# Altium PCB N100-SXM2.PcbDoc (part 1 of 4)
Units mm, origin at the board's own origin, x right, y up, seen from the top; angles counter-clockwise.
Board outline 120 x 145 mm, 4 copper layers (Top Layer, GND, PWR, Bottom Layer), stack 0.603 mm thick; 267 components, 207 nets, 1440 pads, 915 vias.
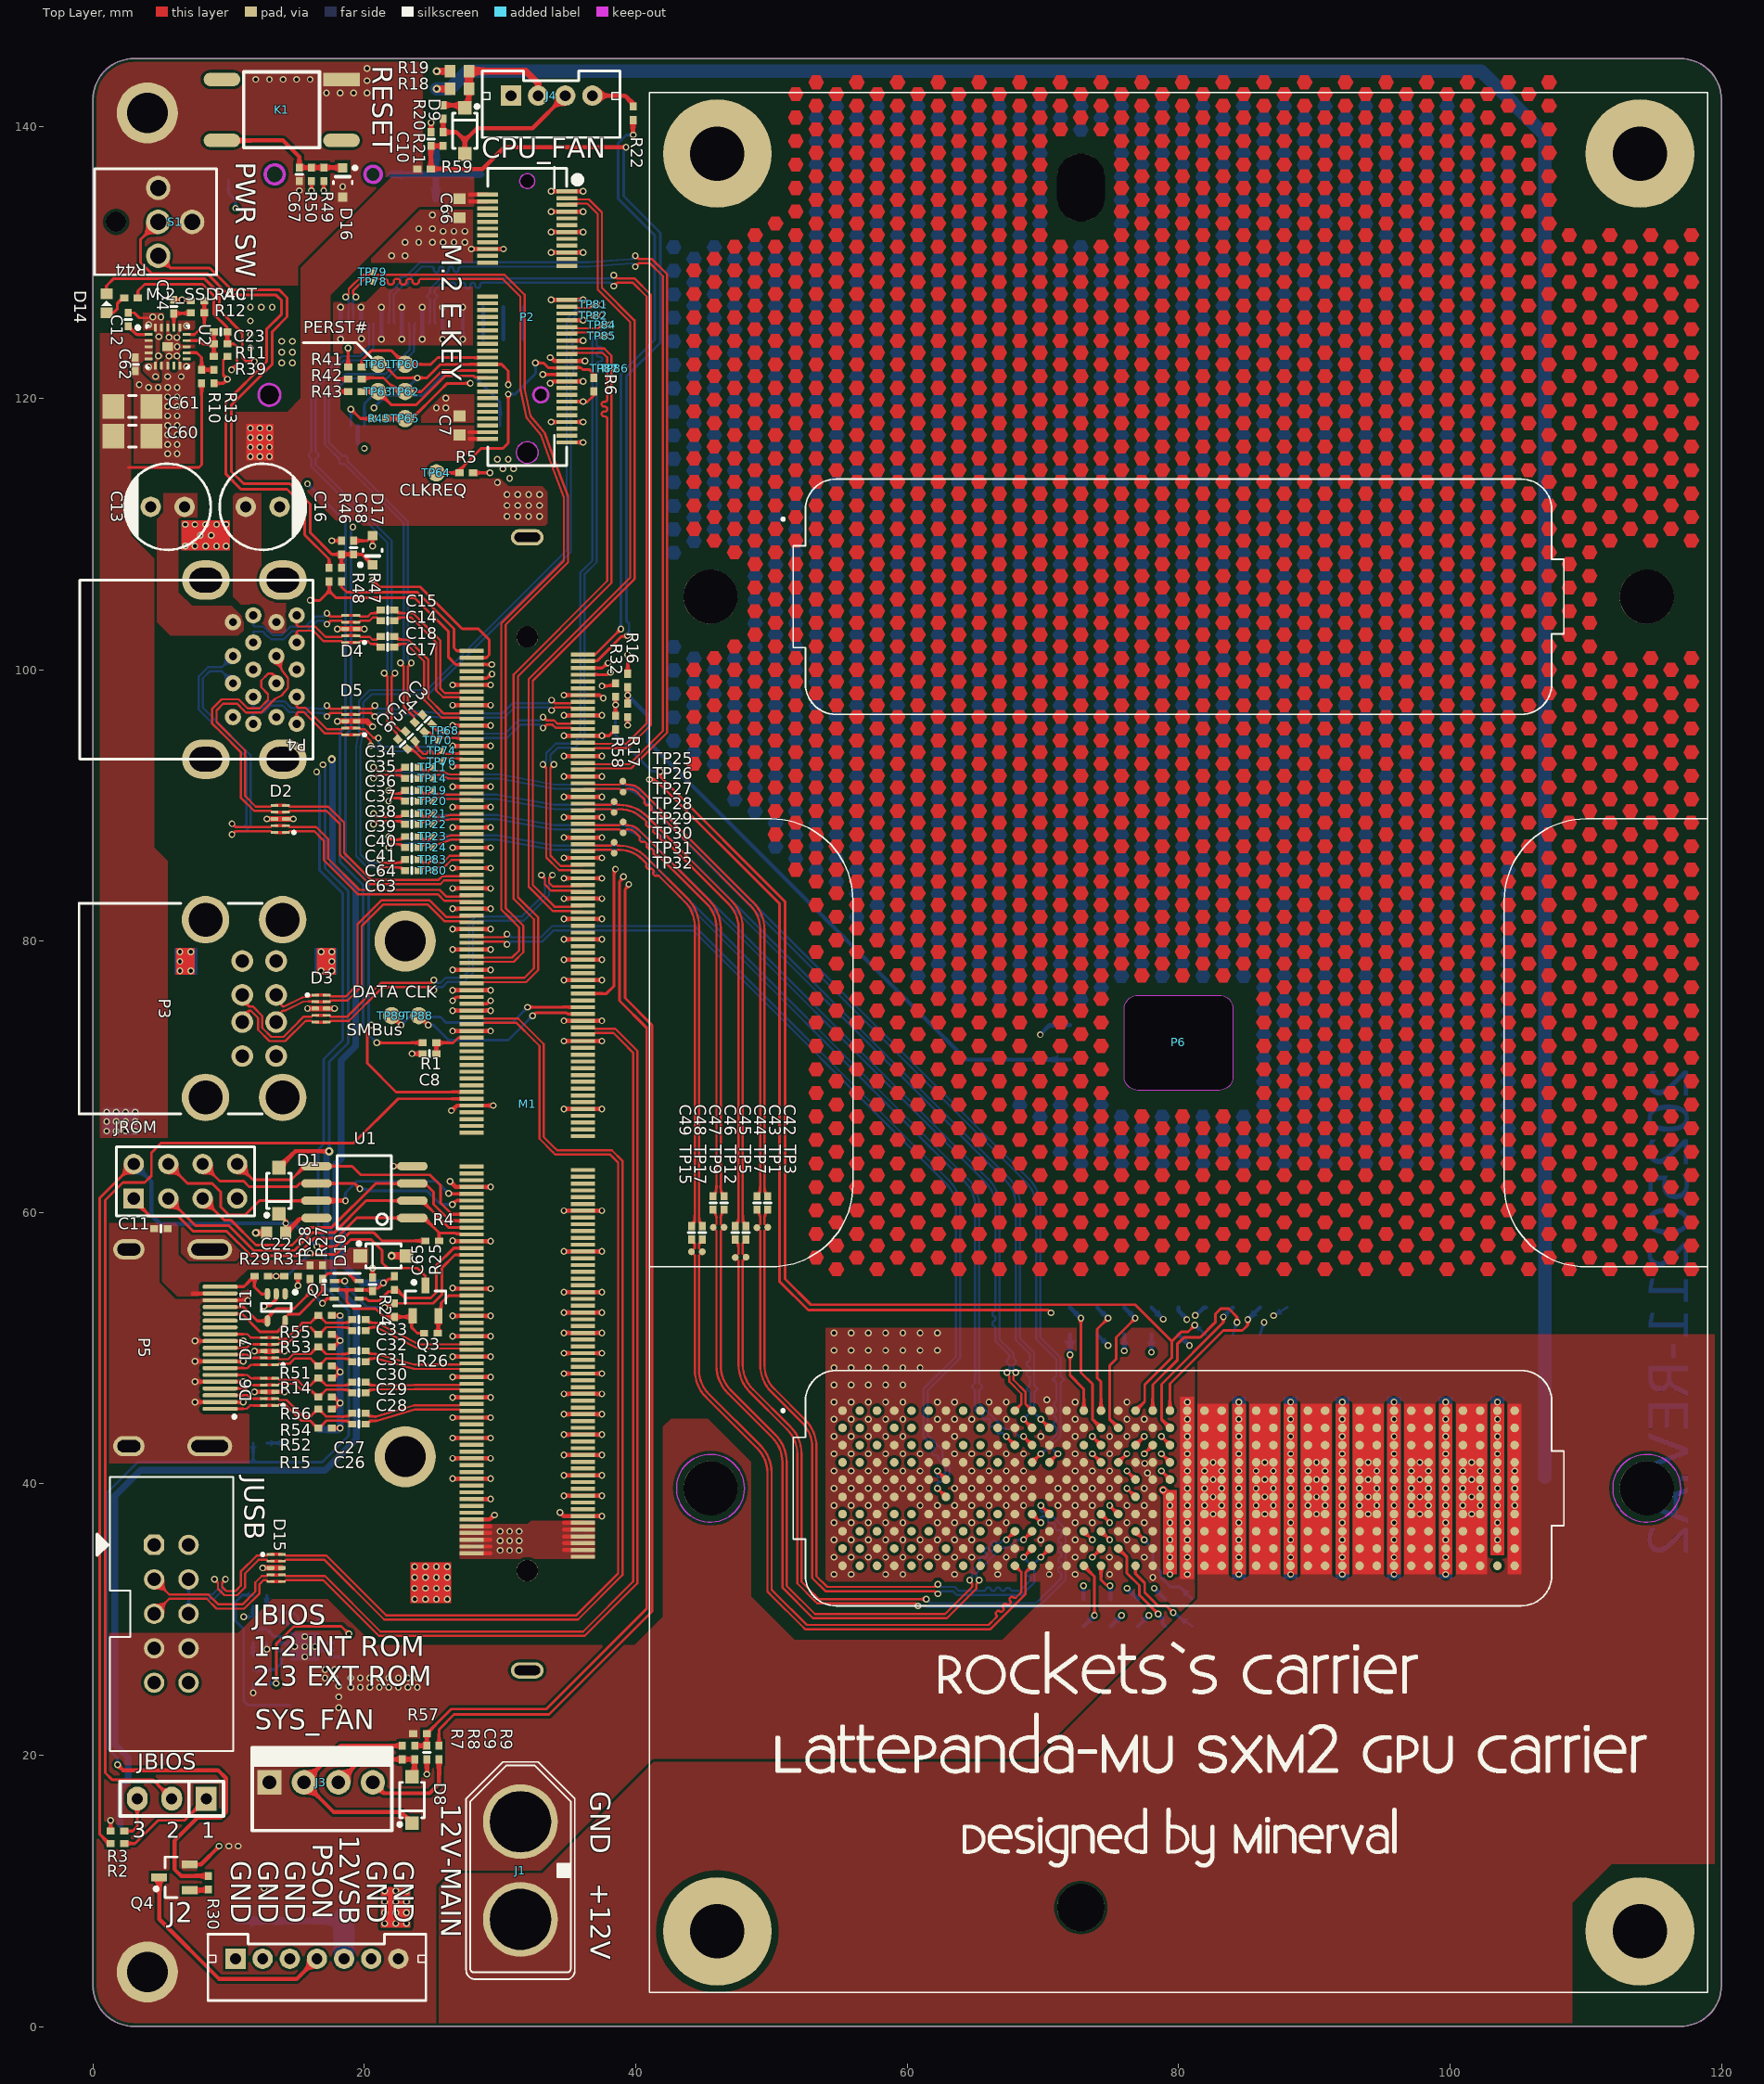
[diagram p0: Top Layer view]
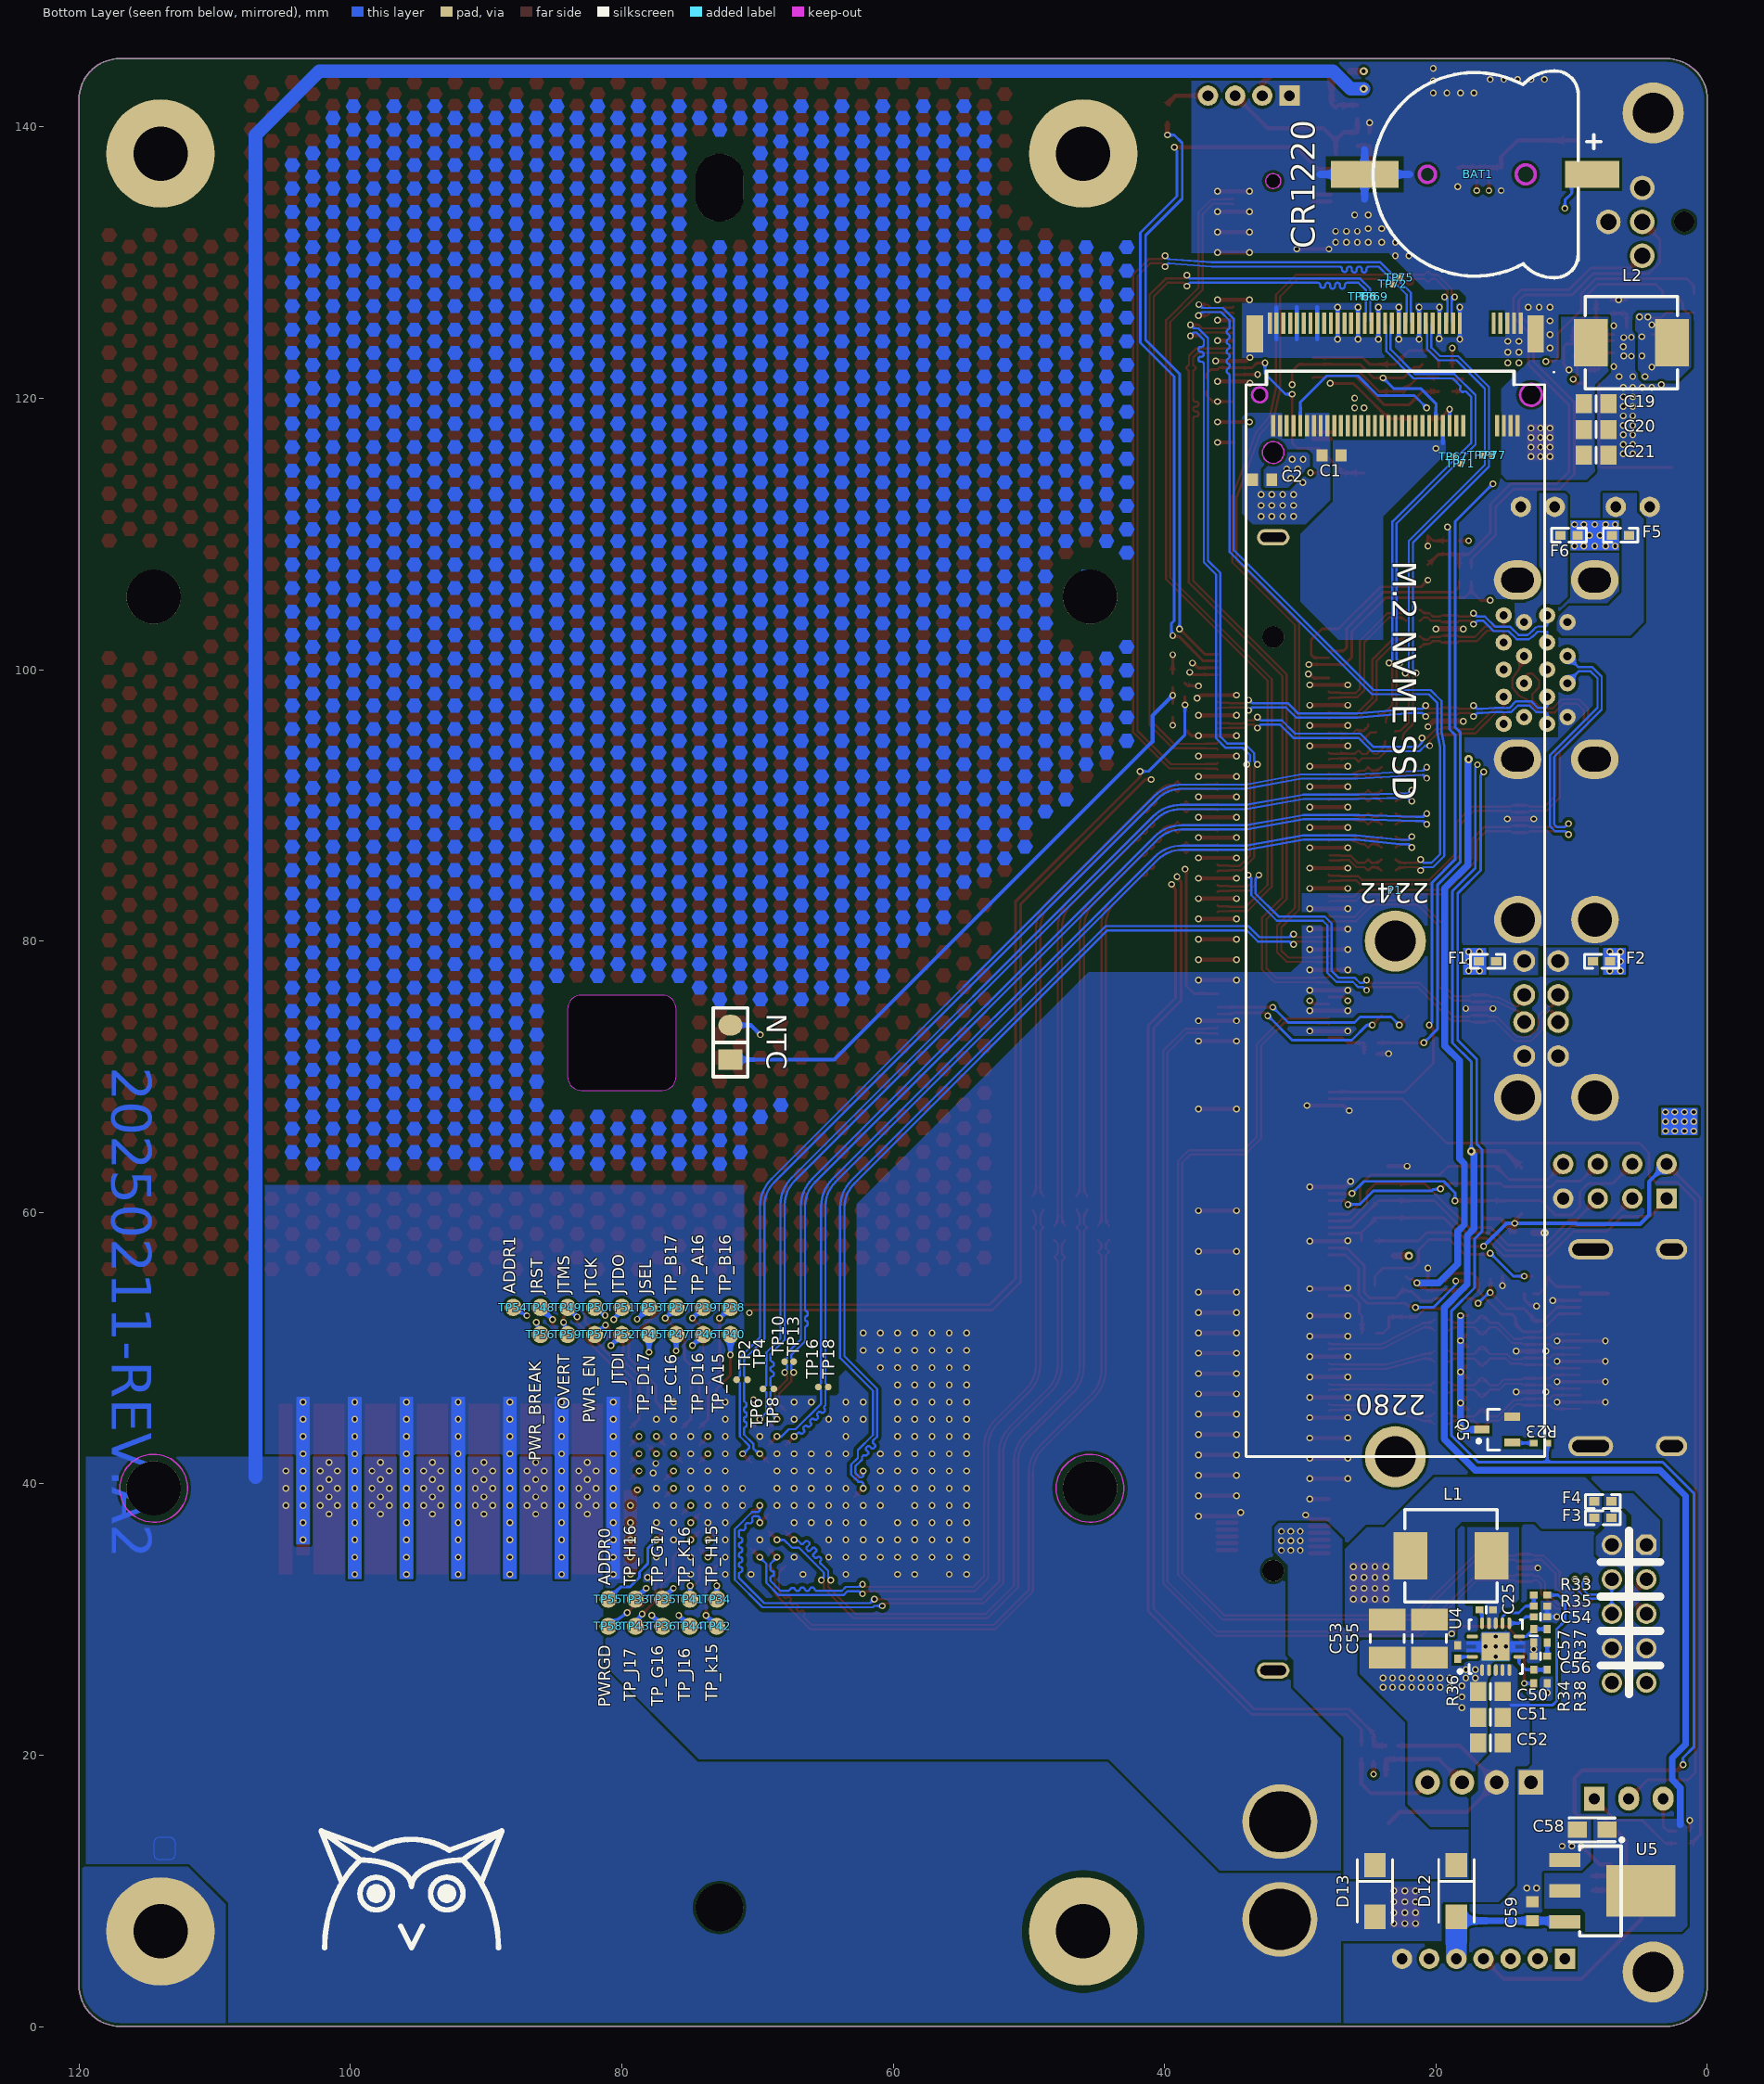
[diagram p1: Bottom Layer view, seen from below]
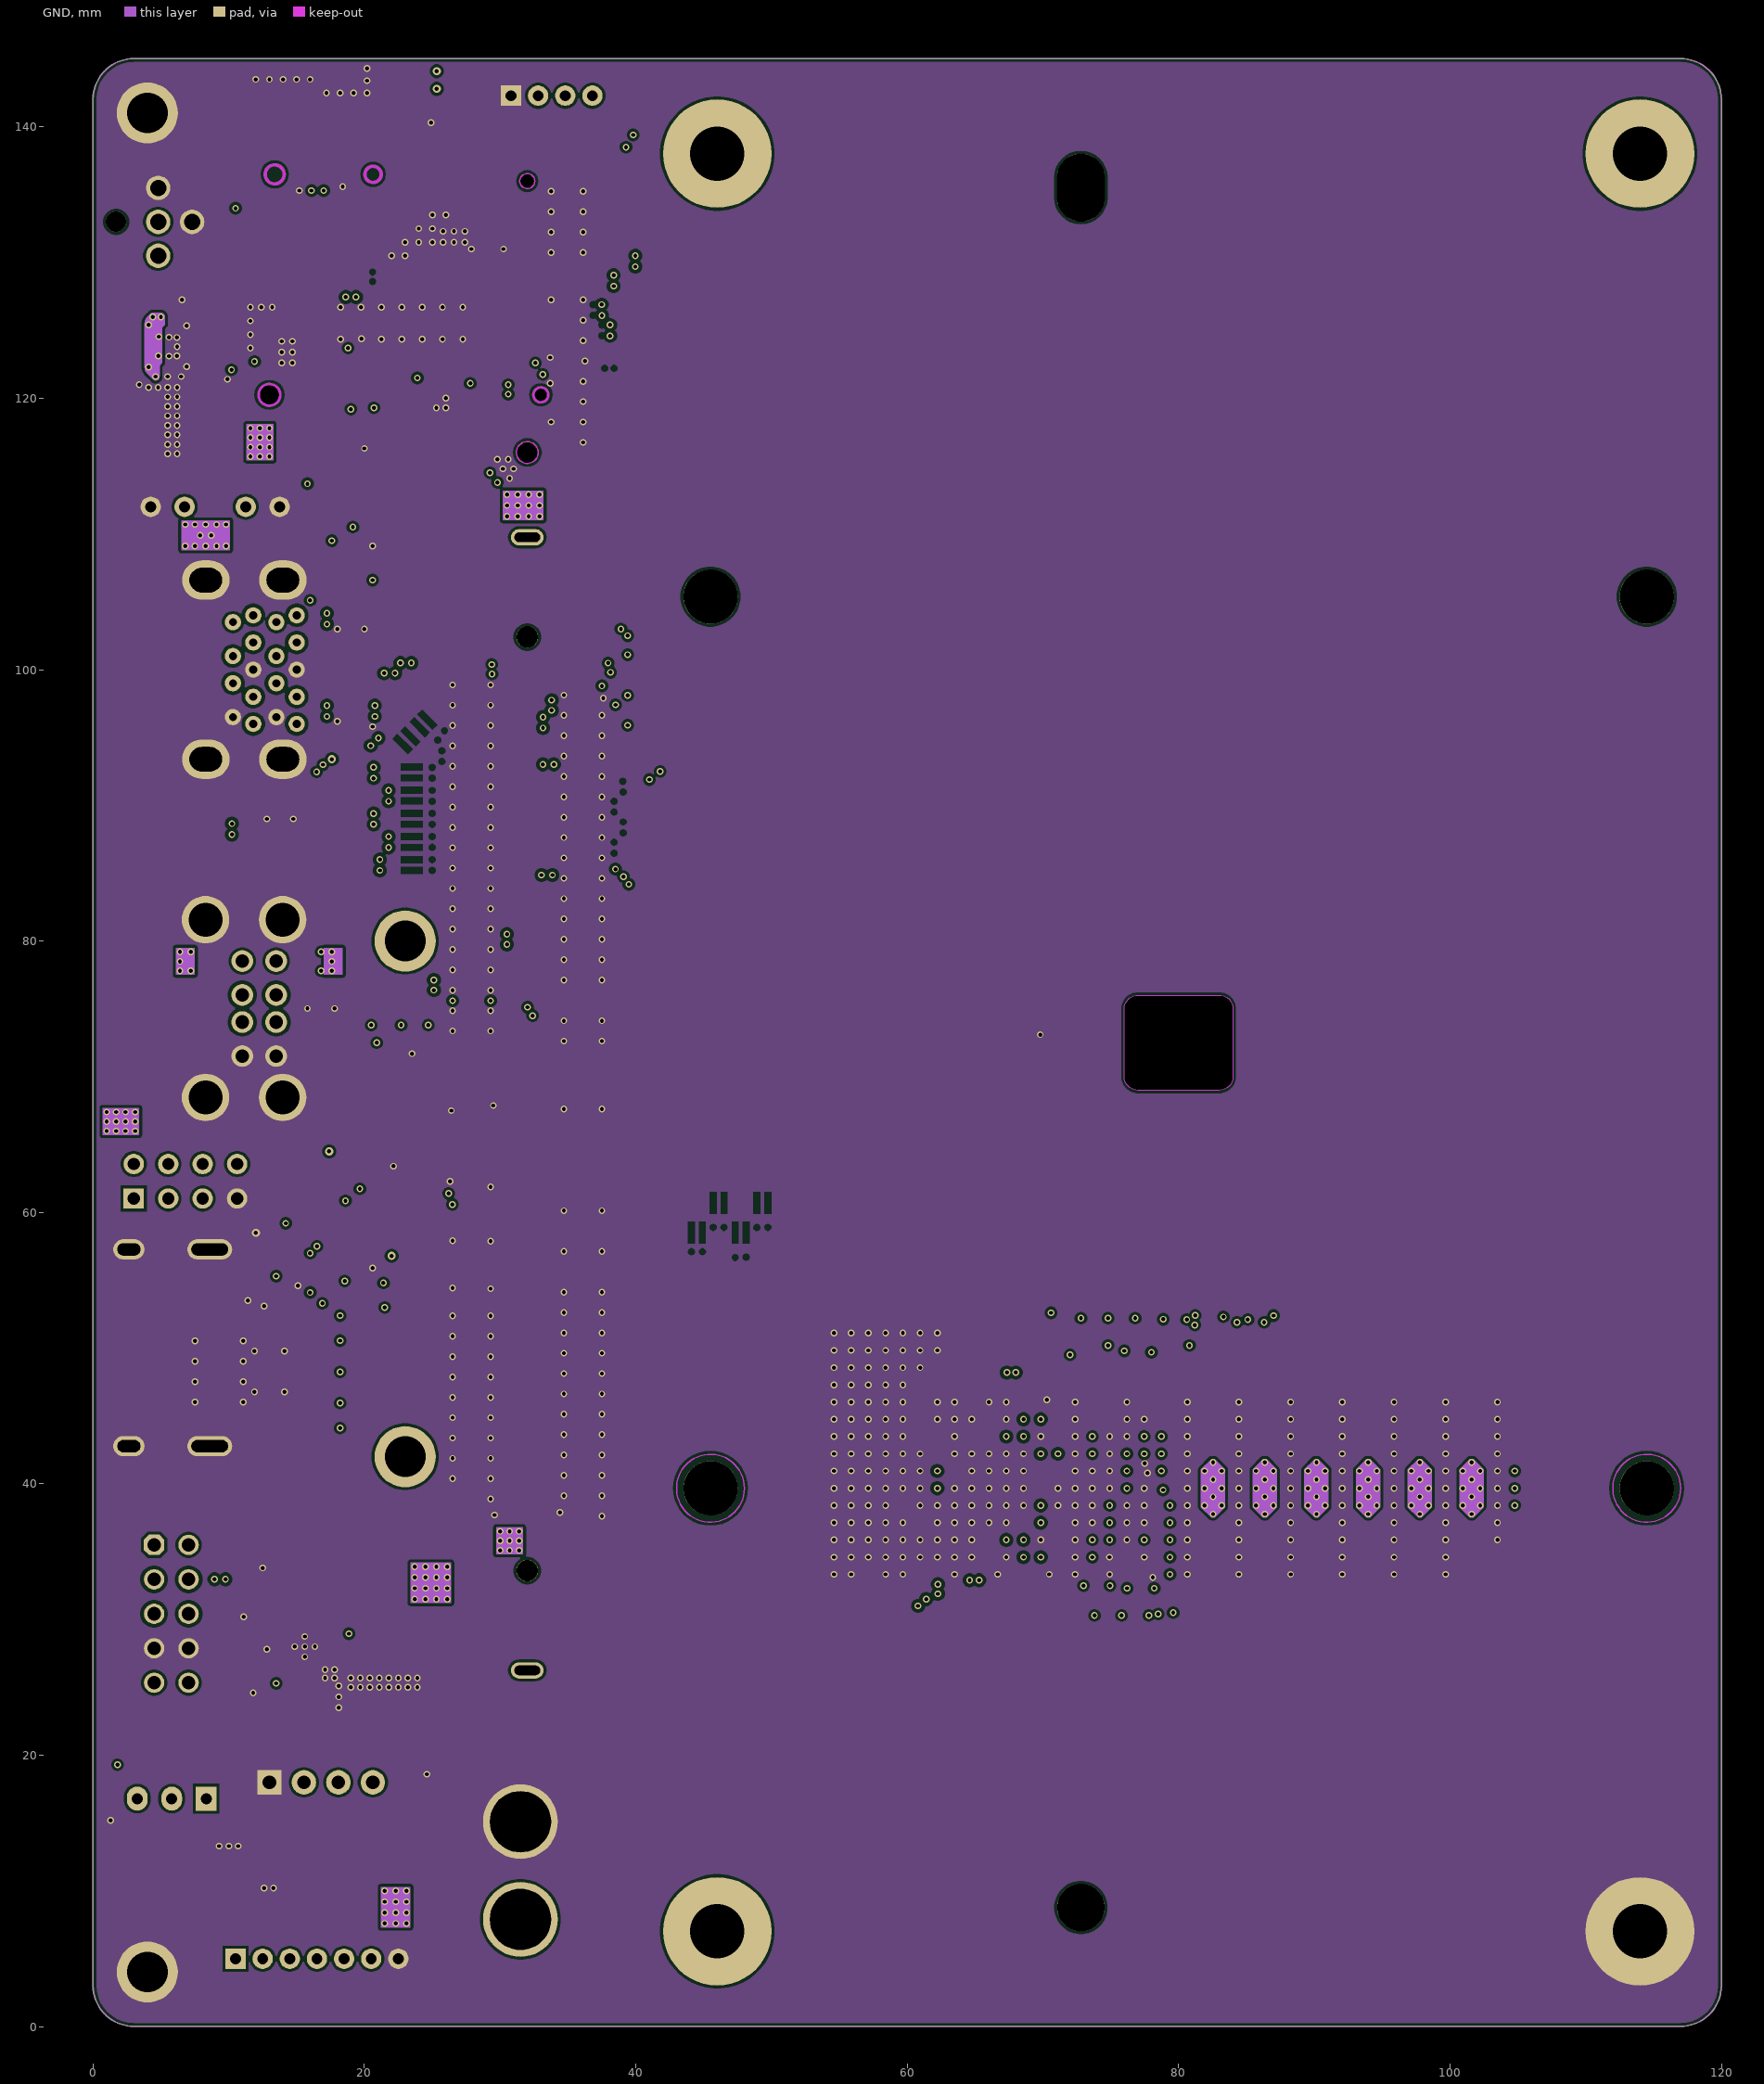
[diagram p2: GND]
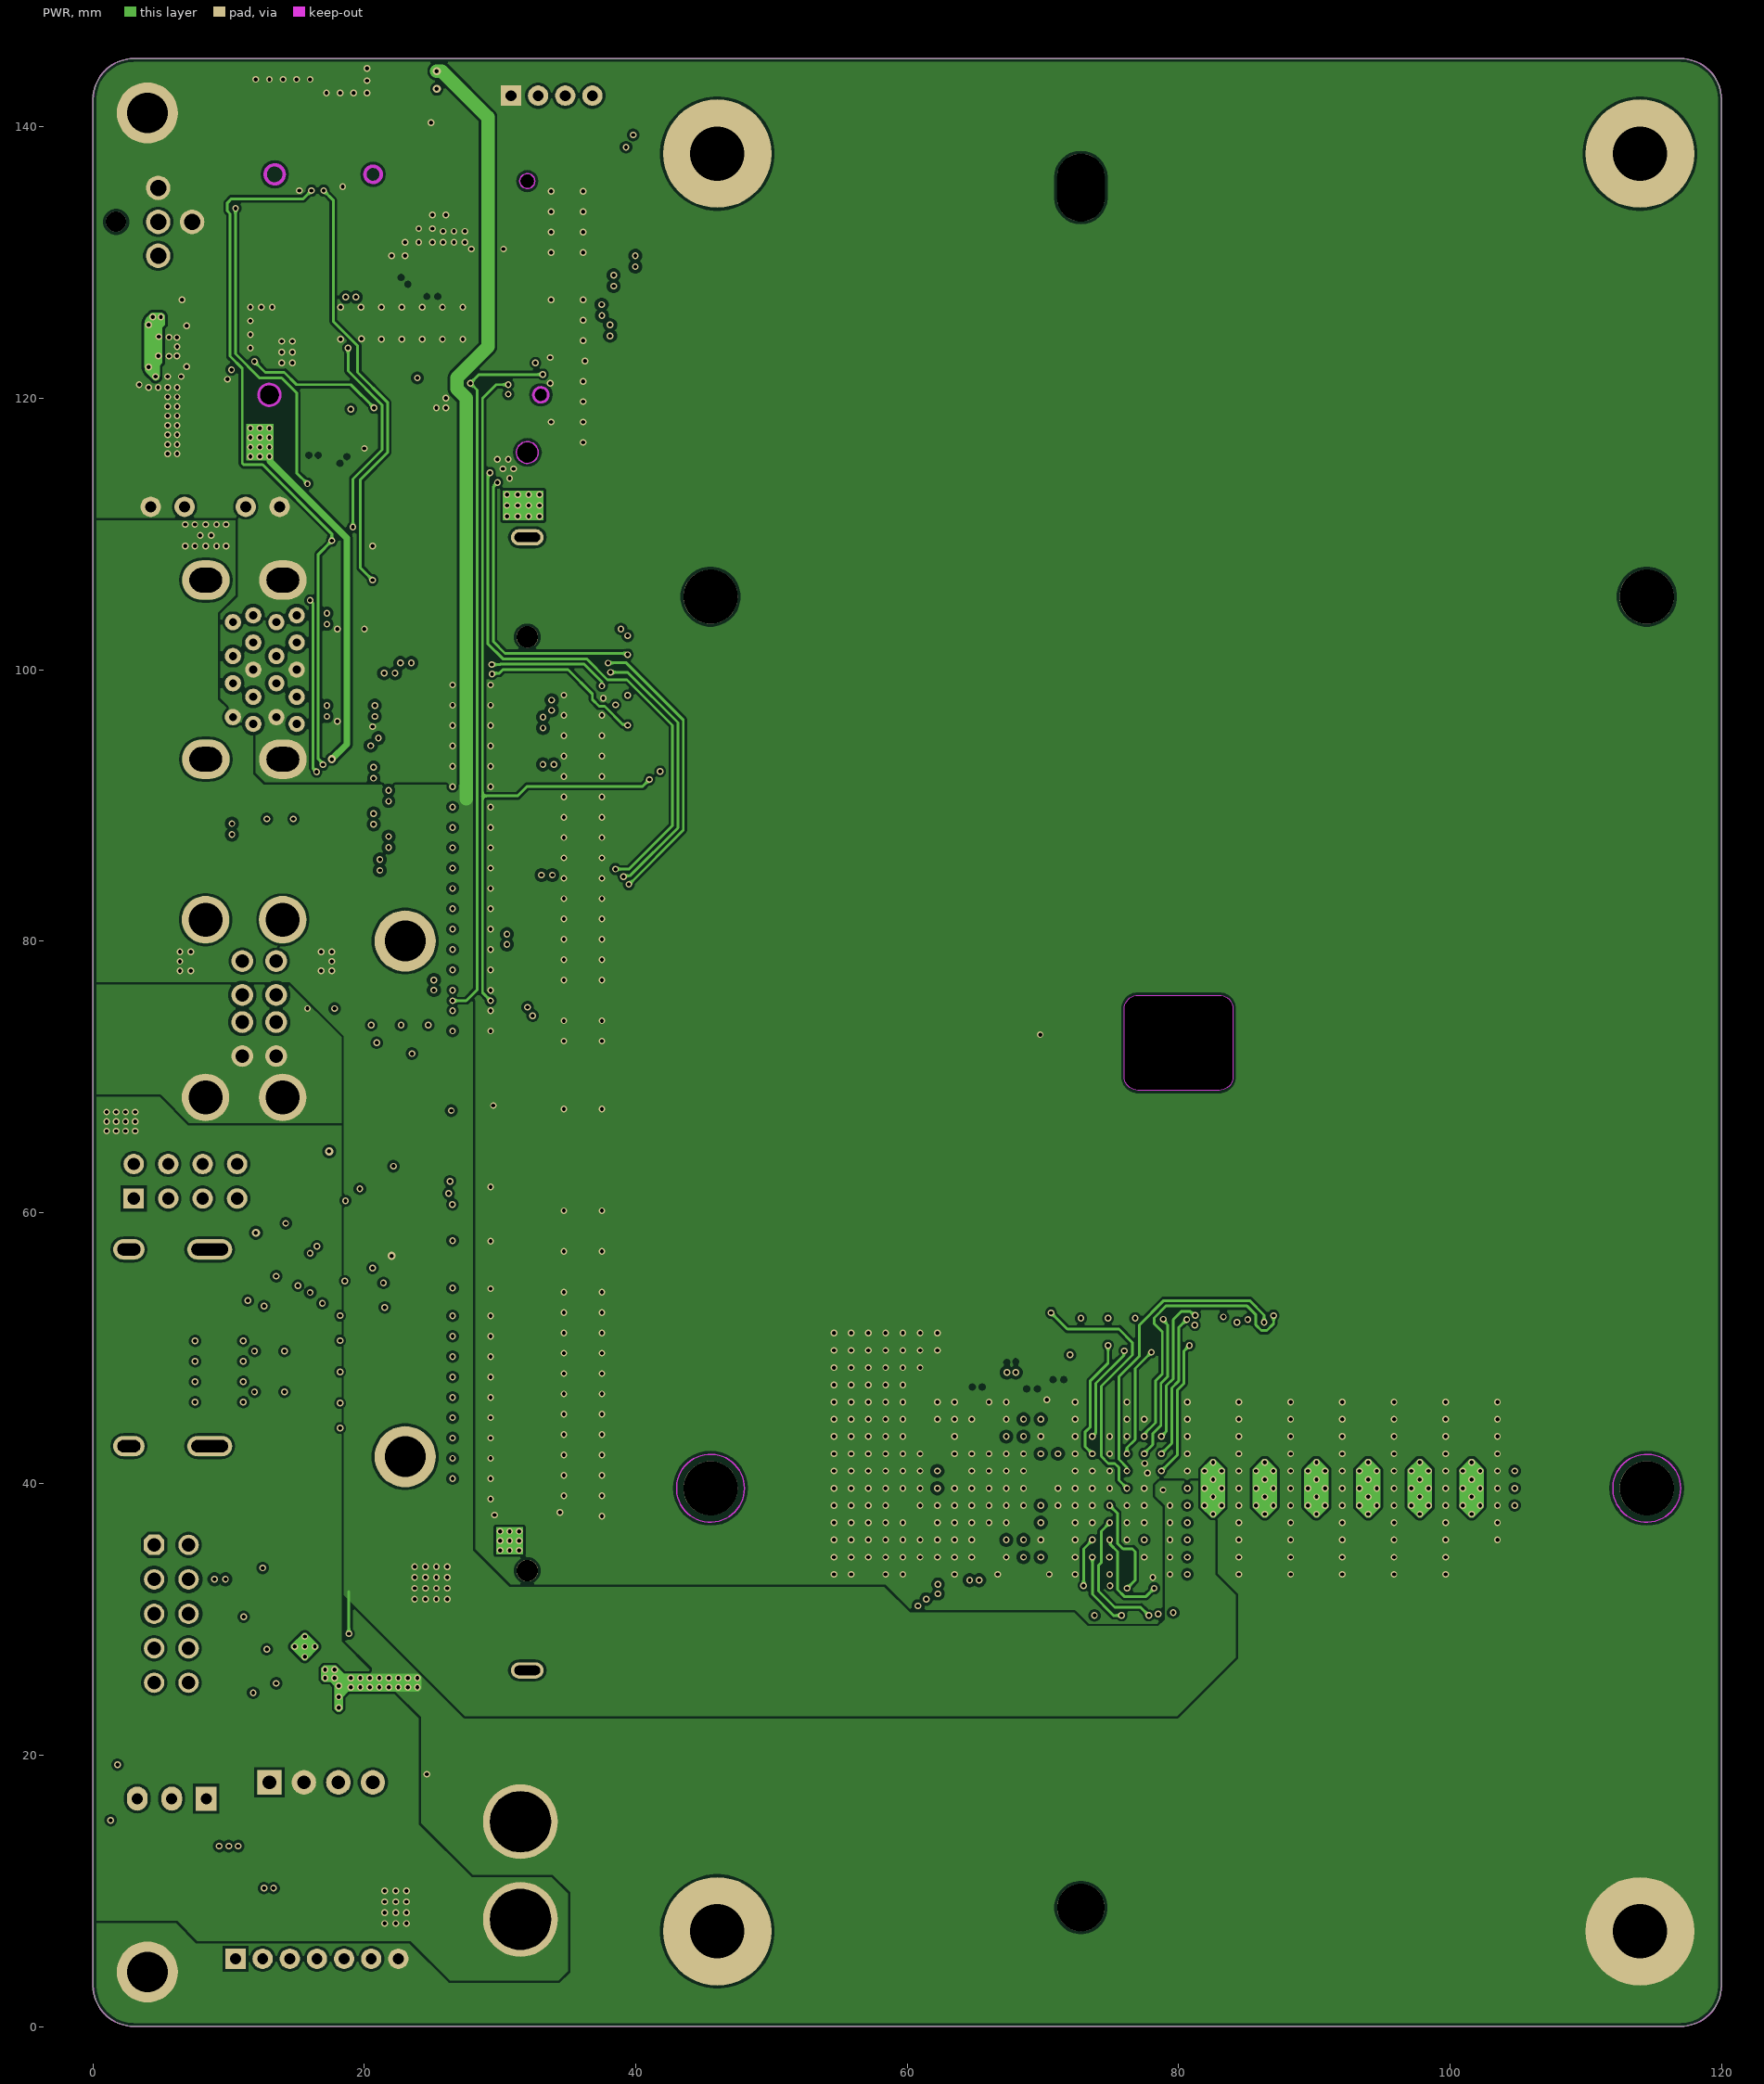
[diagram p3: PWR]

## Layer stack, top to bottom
Top Solder: solder mask 0.0102, Solder Resist, Dk 3.5
Top Layer: signal copper 0.0356
Dielectric 2: prepreg 0.0711, PP-006, Dk 4.1
GND: signal copper 0.035
Dielectric 1: dielectric 0.32, FR-4, Dk 4.8
PWR: signal copper 0.035
Dielectric 3: prepreg 0.0711, PP-006, Dk 4.1
Bottom Layer: signal copper 0.0356
Bottom Solder: solder mask 0.0102, Solder Resist, Dk 3.5

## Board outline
3,0.025 cw(c3,3.025) 0,3.025 0,142.025 cw(c3,142.025) 3,145.025 117,145.025 cw(c117,142.025) 120,142.025 120,3.025 cw(c117,3.025) 117,0.025
cut-out: 77,76 83,76 cw(c83,75) 84,75 84,70 cw(c83,70) 83,69 77,69 cw(c77,70) 76,70 76,75 cw(c77,75)

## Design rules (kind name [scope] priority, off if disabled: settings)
Clearance Clearance_1 [OnLayer('Keep-Out Layer')] p1: gap=0.2 ignorepadtopadclearanceinfootprint=FALSE except(0: Arc-THPad Track-THPad; 0.15: SMDPad-SMDPad)
Clearance HSIO-R85 [InNetClass('HSIO')] p2: gap=0.254 ignorepadtopadclearanceinfootprint=FALSE except(0.15: Arc-Arc Arc-Track Arc-SMDPad Arc-THPad Arc-Via Arc-Region Track-Track Track-SMDPad Track-THPad Track-Via Track-Fill Track-Region SMDPad-SMDPad SMDPad-Via SMDPad-Fill SMDPad-Region THPad-Region Via-Via Via-Region Fill-Region Poly-Region Region-Region)
Clearance [All] p3: gap=0.2 ignorepadtopadclearanceinfootprint=FALSE except(0.15: SMDPad-SMDPad)
DiffPairsRouting [All] p1: maxlimit=0.254 minlimit=0.15 mostfreqgap=0.15 toplayer_minwidth=0.161 toplayer_maxwidth=0.381 toplayer_prefwidth=0.161 midlayer1_minwidth=0.161 midlayer1_maxwidth=0.381 midlayer1_prefwidth=0.161 midlayer2_minwidth=0.161 midlayer2_maxwidth=0.381 midlayer2_prefwidth=0.161 bottomlayer_minwidth=0.161 bottomlayer_maxwidth=0.381 bottomlayer_prefwidth=0.161 maxuncoupledlength=12.7
HoleSize [All] p1: absolutevalues=TRUE maxlimit=5 minlimit=0.3 maxpercent=80.000 minpercent=20.000
MinimumSolderMaskSliver [All] p1 off: minsoldermaskwidth=0.254
PolygonConnect [All] p1: connectstyle=Direct reliefconductorwidth=0.254 reliefentries=4 polygonreliefangle="90 Angle" airgapwidth=0.254
RoutingVias [All] p1: holewidth=0.711 width=1.27 viastyle="Through Hole" minholewidth=0.711 minwidth=1.27 maxholewidth=0.711 maxwidth=1.27
SilkToSilkClearance [All] p1 off: silktosilkclearance=0.254
SilkToSolderMaskClearance [IsPad] p1 off: minsilkscreentomaskgap=0.254 clearancetoexposedcopper=TRUE
SolderMaskExpansion [All] p1: expansion=0.102 istentingtop=FALSE
UnRoutedNet [All] p1: checkbadconnections=TRUE
Width [All] p1: maxlimit=2 minlimit=0.15 preferedwidth=0.254
24 further rules are at their usual default settings.

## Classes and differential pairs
component class SXM-Power: TP33 TP34 TP35 TP36 TP37 TP38 TP39 TP40 TP41 TP42 TP43 TP44 TP45 TP46 TP47
component class PMU: C9 C10 C12 C19 C20 C21 C23 C24 C25 C50 C51 C52 C53 C54 C55 C56 C57 C58 C59 C60 C61 C62 D8 D9 D12 D13 J1 J2 J3 J4 L1 L2 Q4 R7 R8 R9 R10 R11 R12 R13 R18 R19 R20 R21 R22 R30 R33 R34 R35 R36 R37 R38 R39 R40 R57 R59 U2 U4 U5
component class USB: C13 C14 C15 C16 C17 C18 D2 D3 D4 D5 D15 F1 F2 F3 F4 F5 F6 JUSB P3 P4
component class SXM-PCIE: C34 C35 C36 C37 C38 C39 C40 C41 C42 C43 C44 C45 C46 C47 C48 C49 P6 R32 R58 TP1 TP2 TP3 TP4 TP5 TP6 TP7 TP8 TP9 TP10 TP11 TP12 TP13 TP14 TP15 TP16 TP17 TP18 TP19 TP20 TP21 TP22 TP23 TP24 TP25 TP26 TP27 TP28 TP29 TP30 TP31 TP32 TP48 TP49 TP50 TP51 TP52 TP53 TP54 TP55 TP56 TP57 TP58 TP59
component class M.2-PCIE: C1 C2 C3 C4 C5 C6 D14 P1 R44 R45 TP66 TP67 TP68 TP69 TP70 TP71 TP72 TP73 TP74 TP75 TP76 TP77 TP78 TP79
component class GbE: C7 C63 C64 C66 P2 R5 R6 R41 R42 R43 TP60 TP61 TP62 TP63 TP64 TP65 TP80 TP81 TP82 TP83 TP84 TP85 TP86 TP87
component class DP-HDMI: C11 C26 C27 C28 C29 C30 C31 C32 C33 C65 D6 D7 D10 D11 P5 Q1 Q3 Q5 R14 R15 R23 R24 R25 R26 R27 R28 R29 R31 R51 R52 R53 R54 R55 R56
net class HSIO: DDI_B_TX0_N DDI_B_TX0_P DDI_B_TX1_N DDI_B_TX1_P DDI_B_TX2_N DDI_B_TX2_P DDI_B_TX3_N DDI_B_TX3_P HSIO2_RX_n HSIO2_RX_p HSIO2_TX_n HSIO2_TX_p HSIO3_RX_n HSIO3_RX_p HSIO3_TX_n HSIO3_TX_p HSIO6_RX_n HSIO6_RX_p HSIO6_TX_n HSIO6_TX_p HSIO8_RX_n HSIO8_RX_p HSIO8_TX_n HSIO8_TX_p HSIO9_RX_n HSIO9_RX_p HSIO9_TX_n HSIO9_TX_p HSIO10_RX_n HSIO10_RX_p HSIO10_TX_n HSIO10_TX_p HSIO11_RX_n HSIO11_RX_p HSIO11_TX_n HSIO11_TX_p M.2_1_RX0_n M.2_1_RX0_p M.2_1_RX1_n M.2_1_RX1_p M.2_E_n M.2_E_p REFCLK0_n REFCLK0_p REFCLK1_n REFCLK1_p REFCLK2_n REFCLK2_p SXM_PERX0_n SXM_PERX0_p SXM_PERX1_n SXM_PERX1_p SXM_PERX2_n SXM_PERX2_p SXM_PERX3_n SXM_PERX3_p SXM_PETX0_n SXM_PETX0_p SXM_PETX1_n SXM_PETX1_p SXM_PETX2_n SXM_PETX2_p SXM_PETX3_n SXM_PETX3_p TMDS_CK_N TMDS_CK_P TMDS_D0_N TMDS_D0_P TMDS_D1_N TMDS_D1_P TMDS_D2_N TMDS_D2_P USB_1_n USB_1_p USB_2_n USB_2_p USB_3_n USB_3_p USB_4_n USB_4_p USB_F1_n USB_F1_p USB_F2_n USB_F2_p USB_M2_n USB_M2_p USBSS_1_RX_n USBSS_1_RX_p USBSS_1_TX_n USBSS_1_TX_p USBSS_1a_TX_n USBSS_1a_TX_p USBSS_2_RX_n USBSS_2_RX_p USBSS_2_TX_n USBSS_2_TX_p USBSS_2a_TX_n USBSS_2a_TX_p
component class N100-Core: 23 BAT1 C8 C22 C67 C68 D1 D16 D17 JBIOS JROM K1 M1 NTC R1 R2 R3 R4 R16 R17 R46 R47 R48 R49 R50 S1 TP88 TP89 U1
differential pair M.2_E: +M.2_E_p -M.2_E_n
differential pair USB_F2: +USB_F2_p -USB_F2_n
differential pair USB_F1: +USB_F1_p -USB_F1_n
differential pair USB_M2: +USB_M2_p -USB_M2_n
differential pair USB_4: +USB_4_p -USB_4_n
differential pair USB_3: +USB_3_p -USB_3_n
differential pair USBSS_2a_TX: +USBSS_2a_TX_p -USBSS_2a_TX_n
differential pair USBSS_1a_TX: +USBSS_1a_TX_p -USBSS_1a_TX_n
differential pair TMDS_D2: +TMDS_D2_P -TMDS_D2_N
differential pair TMDS_D1: +TMDS_D1_P -TMDS_D1_N
differential pair TMDS_D0: +TMDS_D0_P -TMDS_D0_N
differential pair TMDS_CK: +TMDS_CK_P -TMDS_CK_N
differential pair SXM_PETX3: +SXM_PETX3_p -SXM_PETX3_n
differential pair SXM_PETX2: +SXM_PETX2_p -SXM_PETX2_n
differential pair SXM_PETX1: +SXM_PETX1_p -SXM_PETX1_n
differential pair SXM_PETX0: +SXM_PETX0_p -SXM_PETX0_n
differential pair SXM_PERX3: +SXM_PERX3_p -SXM_PERX3_n
differential pair SXM_PERX2: +SXM_PERX2_p -SXM_PERX2_n
differential pair SXM_PERX1: +SXM_PERX1_p -SXM_PERX1_n
differential pair SXM_PERX0: +SXM_PERX0_p -SXM_PERX0_n
differential pair M.2_1_RX1: +M.2_1_RX1_p -M.2_1_RX1_n
differential pair M.2_1_RX0: +M.2_1_RX0_p -M.2_1_RX0_n
differential pair DDI_B_TX3: +DDI_B_TX3_P -DDI_B_TX3_N
differential pair DDI_B_TX2: +DDI_B_TX2_P -DDI_B_TX2_N
differential pair DDI_B_TX1: +DDI_B_TX1_P -DDI_B_TX1_N
differential pair DDI_B_TX0: +DDI_B_TX0_P -DDI_B_TX0_N
differential pair USB_2: +USB_2_p -USB_2_n
differential pair USB_1: +USB_1_p -USB_1_n
differential pair REFCLK2: +REFCLK2_p -REFCLK2_n
differential pair REFCLK1: +REFCLK1_p -REFCLK1_n
differential pair HSIO11_RX: +HSIO11_RX_p -HSIO11_RX_n
differential pair HSIO9_RX: +HSIO9_RX_p -HSIO9_RX_n
differential pair HSIO8_RX: +HSIO8_RX_p -HSIO8_RX_n
differential pair REFCLK0: +REFCLK0_p -REFCLK0_n
differential pair HSIO11_TX: +HSIO11_TX_p -HSIO11_TX_n
differential pair HSIO9_TX: +HSIO9_TX_p -HSIO9_TX_n
differential pair USBSS_2_TX: +USBSS_2_TX_p -USBSS_2_TX_n
differential pair USBSS_2_RX: +USBSS_2_RX_p -USBSS_2_RX_n
differential pair USBSS_1_TX: +USBSS_1_TX_p -USBSS_1_TX_n
differential pair USBSS_1_RX: +USBSS_1_RX_p -USBSS_1_RX_n
differential pair HSIO8_TX: +HSIO8_TX_p -HSIO8_TX_n
differential pair HSIO10_TX: +HSIO10_TX_p -HSIO10_TX_n
differential pair HSIO10_RX: +HSIO10_RX_p -HSIO10_RX_n
differential pair HSIO6_TX: +HSIO6_TX_p -HSIO6_TX_n
differential pair HSIO6_RX: +HSIO6_RX_p -HSIO6_RX_n
differential pair HSIO3_TX: +HSIO3_TX_p -HSIO3_TX_n
differential pair HSIO3_RX: +HSIO3_RX_p -HSIO3_RX_n
differential pair HSIO2_TX: +HSIO2_TX_p -HSIO2_TX_n
differential pair HSIO2_RX: +HSIO2_RX_p -HSIO2_RX_n

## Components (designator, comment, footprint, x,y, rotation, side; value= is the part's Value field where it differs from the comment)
BAT1 "CR1220" CR1220-A 8.5,136.5 r180 bottom locked
C1 "10uF" C1608-0603#1 27.7,115.8 r0 bottom value=1uF
C2 "10uF" C1608-0603#1 32.8,114 r0 bottom value=1uF
C3 "220nF" C1005-0402#1 24.637,96.319 r315 top value=1uF
C4 "220nF" C1005-0402#1 24.071,95.754 r315 top value=1uF
C5 "220nF" C1005-0402#1 23.383,95.083 r315 top value=1uF
C6 "220nF" C1005-0402#1 22.817,94.517 r315 top value=1uF
C7 "10uF" C1608-0603#1 27,118 r270 top value=1uF
C8 "1uF" C1005-0402#2 24.8,71.7 r0 top
C9 "1nF" C1005-0402#2 24.6,20.2 r90 top value=1uF
C10 "1nF" C1005-0402#2 24.9,139.1 r270 top value=1uF
C11 "100nF" C1005-0402#2 5,58.8 r180 top value=1uF
C12 "100nF" C1005-0402#2 2.6,125.8 r270 top value=1uF
C13 "220uF/10V" C6-6X6MM 5.5,112 r180 top value=10uF
C14 "100nF" C1005-0402#1 21.7,103.6 r0 top value=1uF
C15 "100nF" C1005-0402#1 21.7,104.4 r0 top value=1uF
C16 "220uF/10V" C6-6X6MM 12.5,112 r0 top value=10uF
C17 "100nF" C1005-0402#1 21.7,101.65 r0 top value=1uF
C18 "100nF" C1005-0402#1 21.7,102.45 r0 top value=1uF
C19 "22uF/10V" C2012-0805/Y1.2 8.2,119.6 r0 bottom value=1uF
C20 "22uF/10V" C2012-0805/Y1.2 8.2,117.7 r0 bottom value=1uF
C21 "22uF/10V" C2012-0805/Y1.2 8.2,115.8 r0 bottom value=1uF
C22 "100nF" C1608-0603#2 13.5,58.5 r0 top value=1uF
C23 "56pF" C1005-0402#2 9.4,124.9 r0 top value=1uF
C24 "1uF/10V" C1005-0402#2 5.95,126.75 r270 top value=1uF
C25 "100nF" C1005-0402#2 16.3,30.7 r0 bottom value=1uF
C26 "100nF" C1005-0402#1 19.596,44.4 r0 top value=1uF
C27 "100nF" C1005-0402#1 19.596,45.2 r0 top value=1uF
C28 "100nF" C1005-0402#1 19.596,46.7 r0 top value=1uF
C29 "100nF" C1005-0402#1 19.596,47.5 r0 top value=1uF
C30 "100nF" C1005-0402#1 19.596,49 r0 top value=1uF
C31 "100nF" C1005-0402#1 19.596,49.8 r0 top value=1uF
C32 "100nF" C1005-0402#1 19.596,51.3 r0 top value=1uF
C33 "100nF" C1005-0402#1 19.596,52.1 r0 top value=1uF
C34 "220nF" C1005-0402#1 23.5,92.8 r0 top value=1uF
C35 "220nF" C1005-0402#1 23.5,92 r0 top value=1uF
C36 "220nF" C1005-0402#1 23.5,91.1 r0 top value=1uF
C37 "220nF" C1005-0402#1 23.5,90.3 r0 top value=1uF
C38 "220nF" C1005-0402#1 23.5,89.4 r0 top value=1uF
C39 "220nF" C1005-0402#1 23.5,88.6 r0 top value=1uF
C40 "220nF" C1005-0402#1 23.5,87.7 r0 top value=1uF
C41 "220nF" C1005-0402#1 23.5,86.9 r0 top value=1uF
C42 "220nF" C1005-0402#1 49.725,60.7 r90 top value=1uF
C43 "220nF" C1005-0402#1 48.925,60.7 r90 top value=1uF
C44 "220nF" C1005-0402#1 48.125,58.5 r90 top value=1uF
C45 "220nF" C1005-0402#1 47.325,58.5 r90 top value=1uF
C46 "220nF" C1005-0402#1 46.5,60.7 r90 top value=1uF
C47 "220nF" C1005-0402#1 45.7,60.7 r90 top value=1uF
C48 "220nF" C1005-0402#1 44.9,58.5 r90 top value=1uF
C49 "220nF" C1005-0402#1 44.1,58.5 r90 top value=1uF
C50 "4.7uF/16V" C2012-0805/Y1.2 16,24.7 r180 bottom value=1uF
C51 "4.7uF/16V" C2012-0805/Y1.2 16,22.8 r180 bottom value=1uF
C52 "4.7uF/16V" C2012-0805/Y1.2 16,20.9 r180 bottom value=1uF
C53 "47uF/16V" C3225-1210 23.6,28.6 r90 bottom value=10uF
C54 "1nF" C1005-0402#2 12.3,30.2 r0 bottom value=1uF
C55 "47uF/16V" C3225-1210 20.5,28.6 r90 bottom value=10uF
C56 "12nF" C1005-0402#2 12.3,27.3 r180 bottom value=1uF
C57 "10pF" C1005-0402#2 12.8,28.8 r90 bottom value=1uF
C58 "TC212A226M006Y" TC3216-1206 8.5,14.5 r0 bottom value=10uF
C59 "100nF" C1608-0603#2 12.9,8.5 r270 bottom value=1uF
C60 "22uF/16V" C3216-1206 2.9,117.2 r180 top value=10uF
C61 "22uF/16V" C3216-1206 2.9,119.4 r180 top value=10uF
C62 "100nF" C1005-0402#2 3.1,122.5 r90 top value=1uF
C63 "220nF" C1005-0402#2 23.5,85.2 r0 top value=1uF
C64 "220nF" C1005-0402#2 23.5,86 r0 top value=1uF
C65 "100nF" C1005-0402#2 20.6,54.7 r90 top value=1uF
C66 "10uF" C1608-0603#2 27,134 r90 top value=1uF
C67 "1uF" C1005-0402#2 15.2,136.5 r90 top
C68 "1uF" C1005-0402#2 19.2,109 r270 top
D1 "B5819W SL" SOD-123 13.7,61.6 r90 top
D2 "TPD4E05U06DQAR" DQA0010B#1 13.8,89 r180 top
D3 "TPD4E05U06DQAR" DQA0010B#1 16.8,75.025 r0 top
D4 "TPD4E05U06DQAR" DQA0010B#1 19,103 r180 top
D5 "TPD4E05U06DQAR" DQA0010B#1 19,96.2 r180 top
D6 "TPD4E05U06DQAR" DQA0010B#1 13,46.775 r180 top locked
D7 "TPD4E05U06DQAR" DQA0010B#1 13,49.775 r180 top locked
D8 "B5819W SL" SOD-123 23.5,16.7 r90 top
D9 "B5819W SL" SOD-123 27.4,139.7 r270 top
D10 "B5819W SL" SOD-123 21.4,56.8 r0 top
D11 "PESD5V0L4UG" SC70-5 13.5,53 r270 top
D12 "SL54F" SMAF 18.5,10 r270 bottom
D13 "SL54F" SMAF 24.5,10 r270 bottom
D14 "LED0603-Blue" LED0603-B 1,127 r270 top
D15 "TPD4E05U06DQAR" DQA0010B#2 13.5,33.8 r0 top
D16 "ESD5V0B03-323" SOD-323 18.4,135.9 r270 top
D17 "ESD5V0B03-323" SOD-323 20.6,108.8 r90 top
F1 "BSMD0805-100-6V" "FU 0402" 16.2,78.5 r180 bottom
F2 "BSMD0805-100-6V" "FU 0402" 7.8,78.5 r0 bottom
F3 "BSMD0805-100-6V" "FU 0402" 7.7,37.5 r180 bottom
F4 "BSMD0805-100-6V" "FU 0402" 7.7,38.7 r180 bottom
F5 "BSMD0805-100-6V" "FU 0402" 6.4,109.9 r180 bottom
F6 "BSMD0805-100-6V" "FU 0402" 10.2,109.9 r0 bottom
J1 "XT60PB_M" XT60PB-M 31.5,11.5 r270 top
J2 "PH2.0-7P" PH2.0-7P 10.5,5 r0 top
J3 "KF2510-4P" KF2510-4P 13,18 r0 top
J4 "PH2.0-4P" PH2.0-4P 30.8,142.3 r0 top locked
JBIOS "Pin HDR1X3" "Pin HDR1X3/2.54mm-S" 8.34,16.8 r270 top
JROM "Pin HDR2X4" "Pin HDR2X4/2.54mm-S" 3,61.025 r0 top
JUSB "IDC-10P" IDC2.54-10P 4.5,35.5 r270 top locked
K1 "KEY" SMD-6X6X5 18.218,143.42 r270 top locked
L1 "FXL0630-3R3-M" 06030 18.9,34.7 r0 bottom
L2 "FXL0630-3R3-M" 06030 5.6,124.1 r0 bottom locked
M1 "LattePanda_Mu" ADDR0075 32,68 r90 top locked
NTC "NTC-10K-B3950" "Pin HDR1X2/2.54mm-S" 72,71.26 r0 bottom locked
P1 "M.2-MKEY" M.2-M 23,122 r0 bottom locked
P2 "APCI0143-P001A" APCI0143-P001A 32,126 r270 top locked
P3 "USB2.0 双层" USB-269-BRW 13.97,75.025 r90 top locked
P4 "XUBF-1800-0610" XUBF-1800-0610 8.31,100 r270 top locked
P5 "HDMI-001S" HDMI-001S 0,50.025 r90 top locked
P6 "SXM2 PCIE only" SXM2_PCIEonly 80,72.525 r180 top locked
Q1 "L2N7002DW1T1G" SOT-363 18.7,54.3 r270 top
Q3 "2N7002" SOT-23-N 24.5,53.5 r270 top
Q4 "2N7002" SOT-23-N 6,11 r0 top
Q5 "2SK3018" SOT-23-N 15.5,44 r180 bottom
R1 "1K" R1005-0402#1 24.8,72.5 r0 top
R2 "10K" R1005-0402#1 1.8,13.5 r180 top
R3 "0R" R1005-0402#1 1.8,14.4 r180 top
R4 "100K" R1005-0402#1 25,57.9 r0 top
R5 "NC" R1005-0402#1 27.5,114.5 r0 top
R6 "0R" R1005-0402#1 36.9,121 r270 top
R7 "4.7K" R1005-0402#1 22.8,20.2 r270 top
R8 "27K" R1005-0402#1 23.7,20.2 r90 top
R9 "100R" R1005-0402#1 25.5,20.2 r90 top
R10 "24K" R1005-0402#1 8,121.6 r270 top
R11 "90.9K" R1005-0402#1 9.4,124 r0 top
R12 "330K" R1005-0402#1 7.7,126.3 r180 top
R13 "5.1K" R1005-0402#1 8.9,121.6 r90 top
R14 "47R" R1005-0402#1 17.1,48.7 r180 top
R15 "47R" R1005-0402#1 17.1,44.1 r0 top
R16 "10K/1%" R1005-0402#1 39.4,99.2 r270 top
R17 "0R" R1005-0402#1 39.4,97 r270 top
R18 "NC" R1608-0603 27,142.8 r0 top
R19 "0R" R1608-0603 27,144.1 r0 top
R20 "4.7K" R1005-0402#1 25.8,141.1 r270 top
R21 "27K" R1005-0402#1 25.8,139.1 r270 top
R22 "100R" R1005-0402#1 39.8,141 r270 top
R23 "2.2K" R1005-0402#1 12.3,43 r180 bottom
R24 "2.2K" R1005-0402#1 22.2,52.8 r270 top
R25 "2.2K" R1005-0402#1 22.2,54.8 r90 top
R26 "1M" R1005-0402#1 24.9,51.1 r180 top
R27 "2.2K" R1005-0402#1 16.9,55.6 r90 top
R28 "2.2K" R1005-0402#1 16,55.6 r90 top
R29 "1K" R1005-0402#1 12.4,55.3 r0 top
R30 "10K" R1005-0402#1 8.5,10.6 r90 top
R31 "21.5K" R1005-0402#1 14.6,55.3 r180 top
R32 "13K" R1005-0402#1 38.5,98.5 r270 top
R33 "45.3K" R1005-0402#1 12.3,31.8 r0 bottom
R34 "16.2K" R1005-0402#1 12.8,25.8 r270 bottom
R35 "7.5K" R1005-0402#1 12.3,31 r180 bottom
R36 "93.1K" R1005-0402#1 18.4,27.6 r90 bottom
R37 "10K" R1005-0402#1 11.8,28.8 r270 bottom
R38 "2.2K" R1005-0402#1 11.8,25.8 r90 bottom
R39 "20K" R1005-0402#1 9.4,123.1 r180 top
R40 "5.1K" R1005-0402#1 7.7,127.2 r180 top
R41 "0R" R1005-0402#1 19.3,122.3 r0 top
R42 "10K" R1005-0402#1 19.3,121.4 r0 top
R43 "10K" R1005-0402#1 19.3,120.5 r0 top
R44 "2.2K" R1005-0402#1 2.8,127.4 r180 top
R45 "NC" R1005-0402#1 21.1,118.5 r180 top
R46 "4.7K" R1005-0402#1 18.3,109 r270 top
R47 "100R" R1005-0402#1 18.3,107 r90 top
R48 "1K" R1005-0402#1 17.4,107 r90 top
R49 "100R" R1005-0402#1 17,136.5 r90 top
R50 "4.7K" R1005-0402#1 16.1,136.5 r90 top
R51 "47R" R1005-0402#1 17.1,50.1 r180 top
R52 "47R" R1005-0402#1 17.1,45.5 r0 top
R53 "47R" R1005-0402#1 17.1,51 r180 top
R54 "47R" R1005-0402#1 17.1,46.4 r0 top
R55 "47R" R1005-0402#1 17.1,52.4 r180 top
R56 "47R" R1005-0402#1 17.1,47.8 r0 top
R57 "22K" R1005-0402#1 24.1,21.6 r180 top
R58 "16K" R1005-0402#2 38.5,96.1 r270 top
R59 "NC" R1005-0402#1 24.4,136.9 r180 top
S1 "带灯按键" 带灯按键 4.8,133 r270 top locked
TP1 "TestPoint" TP_HS#1 48.925,58.881 r0 top
TP2 "TestPoint" TP_HS#2 71.545,47.672 r90 bottom
TP3 "TestPoint" TP_HS#1 49.725,58.9 r0 top
TP4 "TestPoint" TP_HS#2 70.744,47.672 r90 bottom
TP5 "TestPoint" TP_HS#1 47.325,56.681 r0 top
TP6 "TestPoint" TP_HS#2 69.6,47 r90 bottom
TP7 "TestPoint" TP_HS#1 48.125,56.7 r0 top
TP8 "TestPoint" TP_HS#2 68.8,47 r90 bottom
TP9 "TestPoint" TP_HS#1 45.7,58.9 r0 top
TP10 "TestPoint" TP_HS#3 68.1,49 r90 bottom
TP11 "TestPoint" TP_HS#1 25,92.8 r90 top
TP12 "TestPoint" TP_HS#1 46.5,58.9 r0 top
TP13 "TestPoint" TP_HS#4 67.246,48.954 r90 bottom
TP14 "TestPoint" TP_HS#1 25,92 r90 top
TP15 "TestPoint" TP_HS#5 44.1,56.321 r180 top
TP16 "TestPoint" TP_HS#6 65.519,46.357 r0 bottom
TP17 "TestPoint" TP_HS#7 44.965,57.1 r90 top
TP18 "TestPoint" TP_HS#2 64.792,47.136 r90 bottom
TP19 "TestPoint" TP_HS#1 25,91.1 r180 top
TP20 "TestPoint" TP_HS#1 25,90.3 r180 top
TP21 "TestPoint" TP_HS#1 25,89.4 r180 top
TP22 "TestPoint" TP_HS#1 25,88.6 r180 top
TP23 "TestPoint" TP_HS#1 25,87.7 r180 top
TP24 "TestPoint" TP_HS#1 25,86.9 r180 top
TP25 "TestPoint" TP_HS#1 39.044,91.775 r90 top
TP26 "TestPoint" TP_HS#1 39.064,90.975 r90 top
TP27 "TestPoint" TP_HS#8 38.4,90.3 r90 top
TP28 "TestPoint" TP_HS#8 38.4,89.5 r90 top
TP29 "TestPoint" TP_HS#1 39.064,88.775 r90 top
TP30 "TestPoint" TP_HS#1 39.064,87.975 r90 top
TP31 "TestPoint" TP_HS#1 38.4,87.275 r90 top
TP32 "TestPoint" TP_HS#1 38.4,86.475 r90 top
TP33 "TestPoint" TP_50mil 79,31.5 r90 bottom
TP34 "TestPoint" TP_50mil 73,31.5 r90 bottom
TP35 "TestPoint" TP_50mil 77,31.5 r90 bottom
TP36 "TestPoint" TP_50mil 77,29.5 r90 bottom
TP37 "TestPoint" TP_50mil 76,53 r90 bottom
TP38 "TestPoint" TP_50mil 72,53 r90 bottom
TP39 "TestPoint" TP_50mil 74,53 r90 bottom
TP40 "TestPoint" TP_50mil 72,51 r90 bottom
TP41 "TestPoint" TP_50mil 75,31.5 r90 bottom
TP42 "TestPoint" TP_50mil 73,29.5 r90 bottom
TP43 "TestPoint" TP_50mil 79,29.5 r90 bottom
TP44 "TestPoint" TP_50mil 75,29.5 r90 bottom
TP45 "TestPoint" TP_50mil 78,51 r90 bottom
TP46 "TestPoint" TP_50mil 74,51 r90 bottom
TP47 "TestPoint" TP_50mil 76,51 r90 bottom
TP48 "TestPoint" TP_50mil 86,53 r90 bottom
TP49 "TestPoint" TP_50mil 84,53 r90 bottom
TP50 "TestPoint" TP_50mil 82,53 r90 bottom
TP51 "TestPoint" TP_50mil 80,53 r90 bottom
TP52 "TestPoint" TP_50mil 80,51 r90 bottom
TP53 "TestPoint" TP_50mil 78,53 r90 bottom
TP54 "TestPoint" TP_50mil 88,53 r90 bottom
TP55 "TestPoint" TP_50mil 81,31.5 r90 bottom
TP56 "TestPoint" TP_50mil 86,51 r90 bottom
TP57 "TestPoint" TP_50mil 82,51 r90 bottom
TP58 "TestPoint" TP_50mil 81,29.5 r90 bottom
TP59 "TestPoint" TP_50mil 84,51 r90 bottom
TP60 "TestPoint" TP_50mil 23,122.5 r90 top
TP61 "TestPoint" TP_50mil 21,122.5 r90 top
TP62 "TestPoint" TP_50mil 23,120.5 r90 top
TP63 "TestPoint" TP_50mil 21,120.5 r90 top
TP64 "TestPoint" TP_50mil 25.3,114.5 r90 top
TP65 "TestPoint" TP_50mil 23,118.5 r90 top
TP66 "TestPoint" TP_HS#9 25.4,127.5 r90 bottom
TP67 "TestPoint" TP_HS#9 18.7,115.7 r90 bottom
TP68 "TestPoint" TP_HS#10 25.9,95.5 r90 top
TP69 "TestPoint" TP_HS#9 24.6,127.5 r90 bottom
TP70 "TestPoint" TP_HS#10 25.4,94.8 r90 top
TP71 "TestPoint" TP_HS#9 18.2,115.2 r90 bottom
TP72 "TestPoint" TP_HS#9 23.2,128.4 r90 bottom
TP73 "TestPoint" TP_HS#9 16.6,115.8 r90 bottom
TP74 "TestPoint" TP_HS#10 25.703,94.025 r90 top
TP75 "TestPoint" TP_HS#9 22.7,128.9 r90 bottom
TP76 "TestPoint" TP_HS#10 25.703,93.225 r90 top
TP77 "TestPoint" TP_HS#9 15.9,115.8 r90 bottom
TP78 "TestPoint" TP_HS#10 20.6,128.6 r90 top
TP79 "TestPoint" TP_HS#10 20.6,129.3 r90 top
TP80 "TestPoint" TP_HS#10 25,85.2 r90 top
TP81 "TestPoint" TP_HS#10 36.855,126.9 r90 top
TP82 "TestPoint" TP_HS#10 36.855,126.1 r90 top
TP83 "TestPoint" TP_HS#10 25,86 r90 top
TP84 "TestPoint" TP_HS#10 37.5,125.4 r90 top
TP85 "TestPoint" TP_HS#10 37.5,124.6 r90 top
TP86 "TestPoint" TP_HS#10 38.4,122.2 r180 top
TP87 "TestPoint" TP_HS#10 37.7,122.2 r180 top
TP88 "TestPoint" TP_50mil 24,74.5 r90 top
TP89 "TestPoint" TP_50mil 22,74.5 r90 top
U1 "W25Q128JVSIQ" SOP-8W 20,61.5 r90 top
U2 "TPS568230RJER" RJE0020A 5.5,123.8 r0 top
U4 "TPS54821RHL" RHL14 15.6,28 r90 bottom
U5 "AMS1117-3.3" SOT223 10.5,10 r270 bottom

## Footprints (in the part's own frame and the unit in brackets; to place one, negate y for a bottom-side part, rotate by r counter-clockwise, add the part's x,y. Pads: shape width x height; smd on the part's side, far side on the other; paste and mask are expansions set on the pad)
06030 [mm]
  rect 2.5x3.5 smd mask+0: 1(-3,0) 2(3,0)
  silkscreen extent -3.4,-3.4 3.4,3.4
ADDR0075 [mm]
  rect 0.3x1.75 smd paste+0 mask+0: 1(33.375,4.1) 2(33.125,-4.1) 3(32.875,4.1) 4(32.625,-4.1) 5(32.375,4.1) 6(32.125,-4.1) 7(31.875,4.1) 8(31.625,-4.1) 9(31.375,4.1) 10(31.125,-4.1) 11(30.875,4.1) 12(30.625,-4.1) 13(30.375,4.1) 14(30.125,-4.1) 15(29.875,4.1) 16(29.625,-4.1) 17(29.375,4.1) 18(29.125,-4.1) 19(28.875,4.1) 20(28.625,-4.1) 21(28.375,4.1) 22(28.125,-4.1) 23(27.875,4.1) 24(27.625,-4.1) 25(27.375,4.1) 26(27.125,-4.1) 27(26.875,4.1) 28(26.625,-4.1) 29(26.375,4.1) 30(26.125,-4.1) 31(25.875,4.1) 32(25.625,-4.1) 33(25.375,4.1) 34(25.125,-4.1) 35(24.875,4.1) 36(24.625,-4.1) 37(24.375,4.1) 38(24.125,-4.1) 39(23.875,4.1) 40(23.625,-4.1) 41(23.375,4.1) 42(23.125,-4.1) 43(22.875,4.1) 44(22.625,-4.1) 45(22.375,4.1) 46(22.125,-4.1) 47(21.875,4.1) 48(21.625,-4.1) 49(21.375,4.1) 50(21.125,-4.1) 51(20.875,4.1) 52(20.625,-4.1) 53(20.375,4.1) 54(20.125,-4.1) 55(19.875,4.1) 56(19.625,-4.1) 57(19.375,4.1) 58(19.125,-4.1) 59(18.875,4.1) 60(18.625,-4.1) 61(18.375,4.1) 62(18.125,-4.1) 63(17.875,4.1) 64(17.625,-4.1) 65(17.375,4.1) 66(17.125,-4.1) 67(16.875,4.1) 68(16.625,-4.1) 69(16.375,4.1) 70(16.125,-4.1) 71(15.875,4.1) 72(15.625,-4.1) 73(15.375,4.1) 74(15.125,-4.1) 75(14.875,4.1) 76(14.625,-4.1) 77(14.375,4.1) 78(14.125,-4.1) 79(13.875,4.1) 80(13.625,-4.1) 81(13.375,4.1) 82(13.125,-4.1) 83(12.875,4.1) 84(12.625,-4.1) 85(12.375,4.1) 86(12.125,-4.1) 87(11.875,4.1) 88(11.625,-4.1) 89(11.375,4.1) 90(11.125,-4.1) 91(10.875,4.1) 92(10.625,-4.1) 93(10.375,4.1) 94(10.125,-4.1) 95(9.875,4.1) 96(9.625,-4.1) 97(9.375,4.1) 98(9.125,-4.1) 99(8.875,4.1) 100(8.625,-4.1) 101(8.375,4.1) 102(8.125,-4.1) 103(7.875,4.1) 104(7.625,-4.1) 105(7.375,4.1) 106(7.125,-4.1) 107(6.875,4.1) 108(6.625,-4.1) 109(6.375,4.1) 110(6.125,-4.1) 111(5.875,4.1) 112(5.625,-4.1) 113(5.375,4.1) 114(5.125,-4.1) 115(4.875,4.1) 116(4.625,-4.1) 117(4.375,4.1) 118(4.125,-4.1) 119(3.875,4.1) 120(3.625,-4.1) 121(3.375,4.1) 122(3.125,-4.1) 123(2.875,4.1) 124(2.625,-4.1) 125(2.375,4.1) 126(2.125,-4.1) 127(1.875,4.1) 128(1.625,-4.1) 129(1.375,4.1) 130(1.125,-4.1) 131(0.875,4.1) 132(0.625,-4.1) 133(0.375,4.1) 134(0.125,-4.1) 135(-0.125,4.1) 136(-0.375,-4.1) 137(-0.625,4.1) 138(-0.875,-4.1) 139(-1.125,4.1) 140(-1.375,-4.1) 141(-1.625,4.1) 142(-1.875,-4.1) 143(-2.125,4.1) 144(-2.375,-4.1) 145(-4.625,4.1) 146(-4.875,-4.1) 147(-5.125,4.1) 148(-5.375,-4.1) 149(-5.625,4.1) 150(-5.875,-4.1) 151(-6.125,4.1) 152(-6.375,-4.1) 153(-6.625,4.1) 154(-6.875,-4.1) 155(-7.125,4.1) 156(-7.375,-4.1) 157(-7.625,4.1) 158(-7.875,-4.1) 159(-8.125,4.1) 160(-8.375,-4.1) 161(-8.625,4.1) 162(-8.875,-4.1) 163(-9.125,4.1) 164(-9.375,-4.1) 165(-9.625,4.1) 166(-9.875,-4.1) 167(-10.125,4.1) 168(-10.375,-4.1) 169(-10.625,4.1) 170(-10.875,-4.1) 171(-11.125,4.1) 172(-11.375,-4.1) 173(-11.625,4.1) 174(-11.875,-4.1) 175(-12.125,4.1) 176(-12.375,-4.1) 177(-12.625,4.1) 178(-12.875,-4.1) 179(-13.125,4.1) 180(-13.375,-4.1) 181(-13.625,4.1) 182(-13.875,-4.1) 183(-14.125,4.1) 184(-14.375,-4.1) 185(-14.625,4.1) 186(-14.875,-4.1) 187(-15.125,4.1) 188(-15.375,-4.1) 189(-15.625,4.1) 190(-15.875,-4.1) 191(-16.125,4.1) 192(-16.375,-4.1) 193(-16.625,4.1) 194(-16.875,-4.1) 195(-17.125,4.1) 196(-17.375,-4.1) 197(-17.625,4.1) 198(-17.875,-4.1) 199(-18.125,4.1) 200(-18.375,-4.1) 201(-18.625,4.1) 202(-18.875,-4.1) 203(-19.125,4.1) 204(-19.375,-4.1) 205(-19.625,4.1) 206(-19.875,-4.1) 207(-20.125,4.1) 208(-20.375,-4.1) 209(-20.625,4.1) 210(-20.875,-4.1) 211(-21.125,4.1) 212(-21.375,-4.1) 213(-21.625,4.1) 214(-21.875,-4.1) 215(-22.125,4.1) 216(-22.375,-4.1) 217(-22.625,4.1) 218(-22.875,-4.1) 219(-23.125,4.1) 220(-23.375,-4.1) 221(-23.625,4.1) 222(-23.875,-4.1) 223(-24.125,4.1) 224(-24.375,-4.1) 225(-24.625,4.1) 226(-24.875,-4.1) 227(-25.125,4.1) 228(-25.375,-4.1) 229(-25.625,4.1) 230(-25.875,-4.1) 231(-26.125,4.1) 232(-26.375,-4.1) 233(-26.625,4.1) 234(-26.875,-4.1) 235(-27.125,4.1) 236(-27.375,-4.1) 237(-27.625,4.1) 238(-27.875,-4.1) 239(-28.125,4.1) 240(-28.375,-4.1) 241(-28.625,4.1) 242(-28.875,-4.1) 243(-29.125,4.1) 244(-29.375,-4.1) 245(-29.625,4.1) 246(-29.875,-4.1) 247(-30.125,4.1) 248(-30.375,-4.1) 249(-30.625,4.1) 250(-30.875,-4.1) 251(-31.125,4.1) 252(-31.375,-4.1) 253(-31.625,4.1) 254(-31.875,-4.1) 255(-32.125,4.1) 256(-32.375,-4.1) 257(-32.625,4.1) 258(-32.875,-4.1) 259(-33.125,4.1) 260(-33.375,-4.1)
  oval 1.2x2.4 hole 0.7 slot 1.9 at 90 deg paste-2539.97 mask+0: 261(-41.75,0) 261(41.75,0)
  round 1.6 hole 1.6 unplated paste-2539.97 mask+0: 261(-34.4,0) 261(34.4,0)
APCI0143-P001A [mm]
  round 1.1 hole 1.1 unplated mask+0: 0(-10,0)
  round 1.6 hole 1.6 unplated mask+0: 0(10,0)
  rect 0.3x1.55 smd mask+0: 1(-9.25,2.93) 2(-9,-2.93) 3(-8.75,2.93) 4(-8.5,-2.93) 5(-8.25,2.93) 6(-8,-2.93) 7(-7.75,2.93) 8(-7.5,-2.93) 9(-7.25,2.93) 10(-7,-2.93) 11(-6.75,2.93) 12(-6.5,-2.93) 13(-6.25,2.93) 14(-6,-2.93) 15(-5.75,2.93) 16(-5.5,-2.93) 17(-5.25,2.93) 18(-5,-2.93) 19(-4.75,2.93) 20(-4.5,-2.93) 21(-4.25,2.93) 22(-4,-2.93) 23(-3.75,2.93) 32(-1.5,-2.93) 33(-1.25,2.93) 34(-1,-2.93) 35(-0.75,2.93) 36(-0.5,-2.93) 37(-0.25,2.93) 38(0,-2.93) 39(0.25,2.93) 40(0.5,-2.93) 41(0.75,2.93) 42(1,-2.93) 43(1.25,2.93) 44(1.5,-2.93) 45(1.75,2.93) 46(2,-2.93) 47(2.25,2.93) 48(2.5,-2.93) 49(2.75,2.93) 50(3,-2.93) 51(3.25,2.93) 52(3.5,-2.93) 53(3.75,2.93) 54(4,-2.93) 55(4.25,2.93) 56(4.5,-2.93) 57(4.75,2.93) 58(5,-2.93) 59(5.25,2.93) 60(5.5,-2.93) 61(5.75,2.93) 62(6,-2.93) 63(6.25,2.93) 64(6.5,-2.93) 65(6.75,2.93) 66(7,-2.93) 67(7.25,2.93) 68(7.5,-2.93) 69(7.75,2.93) 70(8,-2.93) 71(8.25,2.93) 72(8.5,-2.93) 73(8.75,2.93) 74(9,-2.93) 75(9.25,2.93)
  Keep-Out Layer circle w0.1: c-10,0 r0.55
  Keep-Out Layer circle w0.1: c10,0 r0.8
  silkscreen extent -10.95,-2.9 10.95,3.95
C6-6X6MM [mm]
  round 1.5 hole 0.8 paste-2539.97 mask+0: 1(-1.25,0) 2(1.25,0)
  silkscreen extent -3.17,-3.17 3.17,3.17, body extent -3.15,-3.15 3.15,3.15, height 6
C1005-0402#1 [mm] "Chip Capacitor; Body 1.0 x 0.5 mm (LxW typ)"
  rect 0.6x0.508 smd paste+0 mask+0: 1(-0.5,0) 2(0.5,0)
  silkscreen extent 0,-0.25 0,0.25, body extent -0.5,-0.25 0.5,0.25, height 0.5
C1005-0402#2 [mm] "Chip Capacitor; Body 1.0 x 0.5 mm (LxW typ)"
  rect 0.6x0.508 smd mask+0: 1(-0.5,0) 2(0.5,0)
  silkscreen extent 0,-0.25 0,0.25, body extent -0.5,-0.25 0.5,0.25, height 0.5
C1608-0603#1 [mm] "Chip Capacitor; Body 1.6 x 0.8 mm (LxW typ)"
  rect 0.8x0.9 smd paste+0 mask+0: 1(-0.7,0) 2(0.7,0)
  body extent -0.8,-0.4 0.8,0.4, height 0.4
C1608-0603#2 [mm] "Chip Capacitor; Body 1.6 x 0.8 mm (LxW typ)"
  rect 0.8x0.9 smd mask+0: 1(-0.7,0) 2(0.7,0)
  body extent -0.8,-0.4 0.8,0.4, height 0.4
C2012-0805/Y1.2 [mm] "Chip Capacitor, Body 2.0x1.2mm, IPC Medium Density"
  rect 1.2x1.4 smd mask+0: 1(-0.9,0) 2(0.9,0)
  silkscreen extent 0,-0.6 0,0.6, body extent -1,-0.62 1,0.63, height 0.8
C3216-1206 [mm] "Chip Capacitor; Body 3.2 x 1.6 mm (LxW typ)"
  rect 1.6x1.8 smd mask+0: 1(-1.4,0) 2(1.4,0)
  silkscreen extent -0.3,-0.8 0.3,0.8, body extent -1.6,-0.8 1.6,0.8, height 1.6
C3225-1210 [mm] "Chip Capacitor; Body 3.2 x 2.5 mm (LxW typ)"
  rect 1.6x2.7 smd mask+0: 1(-1.4,0) 2(1.4,0)
  silkscreen extent -0.3,-1.25 0.3,1.25, body extent -1.6,-1.25 1.6,1.25, height 2.5
CR1220-A [mm]
  rect 4x2 smd mask+0: 1(0,0)
  rect 5x2 smd mask+0: 2(-16.764,0)
  Keep-Out Layer circle w0.254: c-12.136,0 r0.6
  Keep-Out Layer circle w0.254: c-4.886,0 r0.7
  silkscreen extent -16.13,-7.62 0.64,7.62, body extent -18.77,-7.37 0.99,7.53, height 4.05
DQA0010B#1 [mm]
  rrect50% 0.565x0.2 smd paste+0 mask+0: 1(-0.418,1) 2(-0.418,0.5) 4(-0.418,-0.5) 5(-0.418,-1) 6(0.418,-1) 7(0.418,-0.5) 9(0.418,0.5) 10(0.418,1)
  rrect50% 0.565x0.3 smd paste+0 mask+0: 3(-0.418,0) 8(0.418,0)
  Top Layer region: -0.4,-0.2 0.4,-0.2 0.4,0.2 -0.4,0.2
  silkscreen extent -1.1,0.9 -0.9,1.1, body extent -0.5,-1.25 0.5,1.25, height 0.55
DQA0010B#2 [mm]
  rrect50% 0.565x0.2 smd mask+0: 1(-0.418,1) 2(-0.418,0.5) 4(-0.418,-0.5) 5(-0.418,-1) 6(0.418,-1) 7(0.418,-0.5) 9(0.418,0.5) 10(0.418,1)
  rrect50% 0.565x0.3 smd mask+0: 3(-0.418,0) 8(0.418,0)
  Top Layer region: -0.4,-0.2 0.4,-0.2 0.4,0.2 -0.4,0.2
  silkscreen extent -1.1,0.9 -0.9,1.1, body extent -0.5,-1.25 0.5,1.25, height 0.55
"FU 0402" [mil] "贴片保险丝"
  rect 30x25 smd mask+0: 1(-25,0) 2(25,0)
  silkscreen extent -50,-20 50,20, body extent -20,-10 20,10, height 15
HDMI-001S [mm]
  oval 0.3x2.6 smd paste+0 mask+0: 1(-4.5,-9.36) 2(-4,-9.36) 3(-3.5,-9.36) 4(-3,-9.36) 5(-2.5,-9.36) 6(-2,-9.36) 7(-1.5,-9.36) 8(-1,-9.36) 9(-0.5,-9.36) 10(0,-9.36) 11(0.5,-9.36) 12(1,-9.36) 13(1.5,-9.36) 14(2,-9.36) 15(2.5,-9.36) 16(3,-9.36) 17(3.5,-9.36) 18(4,-9.36) 19(4.5,-9.36)
  oval 1.5x3.3 hole 0.9 slot 2.7 at 90 deg paste-2539.97 mask+0: 20(-7.25,-8.6) 21(7.25,-8.6)
  oval 1.5x2.3 hole 0.9 slot 1.7 at 90 deg paste-2539.97 mask+0: 22(-7.25,-2.64) 23(7.25,-2.64)
  silkscreen extent -5.18,-10.51 -4.98,-10.32, body extent -7.5,-10.02 7.5,2.13, height 6.24
IDC2.54-10P [mm]
  oct 1.5x1.5 hole 1 mask+0: 1(0,0)
  round 1.5 hole 1 mask+0: 2(0,2.54) 3(2.54,0) 4(2.54,2.54) 5(5.08,0) 6(5.08,2.54) 7(7.62,0) 8(7.62,2.54) 9(10.16,0) 10(10.16,2.54)
  silkscreen extent -5,-4.19 15.2,5.84, body extent -5.07,-2.98 15.23,5.87, height 9.13
KF2510-4P [mm]
  rect 1.8x1.8 hole 1 mask+0: 1(0,0)
  round 1.8 hole 1 mask+0: 2(2.54,0) 3(5.08,0) 4(7.62,0)
  silkscreen extent -1.27,-3.56 9.02,2.54, body extent -1.27,-3.59 8.89,2.32, height 11.05
LED0603-B [mm] "Chip LED; Body 1.6 x 0.8 mm (LxW typ)"
  rect 0.8x0.9 smd mask+0: 1(-0.7,0) 2(0.7,0)
  silkscreen extent -0.2,-0.4 0.2,0.4, body extent -0.8,-0.4 0.8,0.4, height 0.6
M.2-M [mm]
  round 1.6 hole 1.6 unplated mask+0: 0(-10,1.75)
  round 4.5 hole 3 mask+0: 0(0,42) 0(0,80)
  round 1.1 hole 1.1 unplated mask+0: 0(10,1.75)
  rect 0.3x1.55 smd mask+0: 1(9.25,-3.525) 2(9,4.025) 3(8.75,-3.525) 4(8.5,4.025) 5(8.25,-3.525) 6(8,4.025) 7(7.75,-3.525) 8(7.5,4.025) 9(7.25,-3.525) 10(7,4.025) 11(6.75,-3.525) 12(6.5,4.025) 13(6.25,-3.525) 14(6,4.025) 15(5.75,-3.525) 16(5.5,4.025) 17(5.25,-3.525) 18(5,4.025) 19(4.75,-3.525) 20(4.5,4.025) 21(4.25,-3.525) 22(4,4.025) 23(3.75,-3.525) 24(3.5,4.025) 25(3.25,-3.525) 26(3,4.025) 27(2.75,-3.525) 28(2.5,4.025) 29(2.25,-3.525) 30(2,4.025) 31(1.75,-3.525) 32(1.5,4.025) 33(1.25,-3.525) 34(1,4.025) 35(0.75,-3.525) 36(0.5,4.025) 37(0.25,-3.525) 38(0,4.025) 39(-0.25,-3.525) 40(-0.5,4.025) 41(-0.75,-3.525) 42(-1,4.025) 43(-1.25,-3.525) 44(-1.5,4.025) 45(-1.75,-3.525) 46(-2,4.025) 47(-2.25,-3.525) 48(-2.5,4.025) 49(-2.75,-3.525) 50(-3,4.025) 51(-3.25,-3.525) 52(-3.5,4.025) 53(-3.75,-3.525) 54(-4,4.025) 55(-4.25,-3.525) 56(-4.5,4.025) 57(-4.75,-3.525) 58(-5,4.025) 67(-7.25,-3.525) 68(-7.5,4.025) 69(-7.75,-3.525) 70(-8,4.025) 71(-8.25,-3.525) 72(-8.5,4.025) 73(-8.75,-3.525) 74(-9,4.025) 75(-9.25,-3.525)
  rect 1.2x2.75 smd mask+0: 76(10.35,-2.75) 77(-10.35,-2.75)
  Keep-Out Layer circle w0.2: c10,1.75 r0.55
  Keep-Out Layer circle w0.2: c-10,1.75 r0.8
  silkscreen extent -8.75,0 9.5,1, body extent -10.93,-4.08 10.92,4.08, height 4.75
PH2.0-4P [mm]
  rect 1.5x1.5 hole 0.8 mask+0: 1(0,0)
  round 1.5 hole 0.8 mask+0: 2(2,0) 3(4,0) 4(6,0)
  silkscreen extent -2.13,-3.08 8.03,1.82, body extent -1.93,-3.01 7.97,1.69, height 6.01
PH2.0-7P [mm]
  rect 1.5x1.5 hole 0.8 mask+0: 1(0,0)
  round 1.5 hole 0.8 mask+0: 2(2,0) 3(4,0) 4(6,0) 5(8,0) 6(10,0) 7(12,0)
  silkscreen extent -2.03,-3.08 14.03,1.82, body extent -1.95,-3.02 13.95,1.68, height 6.01
"Pin HDR1X2/2.54mm-S" [mil]
  rect 70x60 smd mask+0: 1(0,0)
  oval 70x60 smd mask+0: 2(0,-100)
  silkscreen extent -50,-150 50,50
"Pin HDR1X3/2.54mm-S" [mil]
  rect 70x60 hole 32 mask+0: 1(0,0)
  oval 70x60 hole 32 mask+0: 2(0,-100) 3(0,-200)
  silkscreen extent -50,-250 50,50, body extent -50,-250 50,50, height 336
"Pin HDR2X4/2.54mm-S" [mm] "Connector; Header; 4x2 Position"
  rect 1.5x1.5 hole 0.9 mask+0: 1(0,0)
  round 1.5 hole 0.9 mask+0: 2(0,2.54) 3(2.54,0) 4(2.54,2.54) 5(5.08,0) 6(5.08,2.54) 7(7.62,0) 8(7.62,2.54)
  silkscreen extent -1.27,-1.27 8.89,3.81, body extent -1.27,-1.27 8.89,3.81, height 7.58
R1005-0402#1 [mm]
  rect 0.6x0.508 smd mask+0: 1(-0.5,0) 2(0.5,0)
  body extent -0.5,-0.25 0.5,0.25, height 0.35
R1005-0402#2 [mm]
  rect 0.6x0.508 smd: 1(-0.5,0) 2(0.5,0)
  body extent -0.5,-0.25 0.5,0.25, height 0.35
R1608-0603 [mm] "Chip Resistor; Body 1.6 x 0.8 mm (LxW typ)"
  rect 0.8x0.9 smd mask+0: 1(-0.7,0) 2(0.7,0)
  body extent -0.8,-0.45 0.8,0.45, height 0.5
RHL14 [mm]
  oval 0.28x0.85 smd paste-0.025 mask+0: 1(-0.75,1.725) 7(-0.75,-1.725) 8(0.75,-1.725) 14(0.75,1.725)
  oval 0.85x0.28 smd paste-0.025 mask+0: 2(-1.725,1) 3(-1.725,0.5) 4(-1.725,0) 5(-1.725,-0.5) 6(-1.725,-1) 9(1.725,-1) 10(1.725,-0.5) 11(1.725,0) 12(1.725,0.5) 13(1.725,1)
  rect 2.05x2.05 smd paste-2 mask+0: 15(0,0)
  Top Layer region: 0.39,2.15 0.16,2.15 0.16,1.425 -0.16,1.425 -0.16,2.15 -0.39,2.15 -0.39,1.025 -1.025,1.025 -1.025,-1.025 -0.39,-1.025 -0.39,-2.15 -0.16,-2.15 -0.16,-1.425 0.16,-1.425 0.16,-2.15 0.39,-2.15 0.39,-1.025 1.025,-1.025 1.025,1.025 0.39,1.025
  silkscreen extent -1.97,-1.97 1.97,2.75, body extent -1.75,-1.75 1.75,1.75, height 1
RJE0020A [mm] "PQFN, 20-Leads, Body 3.00x3.00mm, Pitch 0.45mm, Thermal Pad 0.76x0.68mm, IPC Medium Density"
  rrect50% 0.6x0.2 smd paste+0.05 mask+0: 1(-1.4,0.9) 2(-1.4,0.45) 3(-1.4,0) 4(-1.4,-0.45) 5(-1.4,-0.9) 11(1.4,-0.9) 12(1.4,-0.45) 13(1.4,0) 14(1.4,0.45) 15(1.4,0.9)
  rrect50% 0.2x0.6 smd paste+0.05 mask+0: 6(-0.9,-1.4) 7(-0.45,-1.4) 8(0,-1.4) 9(0.45,-1.4) 10(0.9,-1.4) 16(0.9,1.4) 17(0.45,1.4) 18(0,1.4) 19(-0.45,1.4) 20(-0.9,1.4)
  rrect5% 0.76x0.675 smd paste+0.05 mask+0: 21(0,0)
  silkscreen extent -2.32,-1.55 1.55,1.55, body extent -1.55,-1.55 1.55,1.55, height 1
SC70-5 [mm]
  oval 0.85x0.4 smd mask+0: 1(-1,0.65) 2(-1,0) 3(-1,-0.65) 4(1,-0.65) 5(1,0.65)
  silkscreen extent -1.25,-1.1 0.3,1.53, body extent -1.05,-1 1.05,1, height 1
SMAF [mm]
  rect 1.8x1.6 smd mask+0: 1(-1.9,0) 2(1.9,0)
  silkscreen extent -2.3,-1.3 2.3,1.3, body extent -2.32,-1.3 2.32,1.3, height 1.08
SMD-6X6X5 [mm]
  rect 1x2.7 smd mask+0: 1(-0.08,0.082)
  oval 1x2.7 smd mask+0: 2(4.42,0.082) 3(-0.08,-8.718) 4(4.42,-8.718)
  silkscreen extent -0.63,-7.11 4.95,-1.52, body extent -0.79,-8.82 5.21,0.18, height 4.95
SOD-123 [mm]
  rect 1x1 smd mask+0: 1(-1.7,0) 2(1.7,0)
  silkscreen extent -1.92,-0.9 1.3,1.02, body extent -1.95,-0.9 1.95,0.9, height 1.18
SOD-323 [mm]
  rect 0.7x0.7 smd mask+0: 1(-1.075,0) 2(1.075,0)
  silkscreen extent -1.2,-0.7 0.1,1.03, body extent -1.3,-0.67 1.3,0.68, height 1.1
SOP-8W [mm]
  oval 0.63x2.25 smd mask+0: 1(-1.905,-3.53) 2(-0.635,-3.53) 3(0.635,-3.53) 4(1.905,-3.53) 5(1.905,3.53) 6(0.635,3.53) 7(-0.635,3.53) 8(-1.905,3.53)
  silkscreen extent -2.7,-2 2.7,2, body extent -2.62,-3.99 2.62,3.99, height 1.89
SOT223 [mil]
  rect 40x90 smd mask+0: 1(-90,0) 2(0,0) 3(90,0)
  rect 150x200 smd mask+0: 2(0,220)
  silkscreen extent -130,43 130,163, body extent -130,-30 126,246, height 65
SOT-23-N [mm] "SOT23, 3-Leads, Body 2.9x1.3mm, Pitch 0.95mm, Lead Span 2.3mm - Reverse Pinning, IPC Medium Density"
  rect 1.15x0.6 smd mask+0: 1(1.125,-0.95) 2(1.125,0.95) 3(-1.125,0)
  silkscreen extent -1.47,-1.5 0.2,1.5, body extent -1.25,-1.5 1.25,1.5, height 1.06
SOT-363 [mm]
  rect 0.3x0.66 smd mask+0: 1(-0.65,-0.92) 2(0,-0.92) 3(0.65,-0.92) 4(0.65,0.92) 5(0,0.92) 6(-0.65,0.92)
  silkscreen extent -1.2,-1.75 1.2,1, body extent -1.1,-1.2 1.1,1.2, height 1.1
SXM2_PCIEonly [mm]
  round 0.64 smd paste+0 mask+0: A1(24.765,27.135) A2(23.495,27.135) A3(22.225,27.135) A4(20.955,27.135) A5(19.685,27.135) A6(18.415,27.135) A7(17.145,27.135) A8(15.875,27.135) A9(14.605,27.135) A10(13.335,27.135) A11(12.065,27.135) A12(10.795,27.135) A13(9.525,27.135) A14(8.255,27.135) A15(6.985,27.135) A16(5.715,27.135) A17(4.445,27.135) A18(3.175,27.135) A19(1.905,27.135) A20(0.635,27.135) A21(-0.635,27.135) A22(-1.905,27.135) A23(-3.175,27.135) A24(-4.445,27.135) A25(-5.715,27.135) A26(-6.985,27.135) A27(-8.255,27.135) A28(-9.525,27.135) A29(-10.795,27.135) A30(-12.065,27.135) A31(-13.335,27.135) A32(-14.605,27.135) A33(-15.875,27.135) A34(-17.145,27.135) A35(-18.415,27.135) A36(-19.685,27.135) A37(-20.955,27.135) A38(-22.225,27.135) A39(-23.495,27.135) A40(-24.765,27.135) B1(24.765,28.405) B2(23.495,28.405) B3(22.225,28.405) B4(20.955,28.405) B5(19.685,28.405) B6(18.415,28.405) B7(17.145,28.405) B8(15.875,28.405) B9(14.605,28.405) B10(13.335,28.405) B11(12.065,28.405) B12(10.795,28.405) B13(9.525,28.405) B14(8.255,28.405) B15(6.985,28.405) B16(5.715,28.405) B17(4.445,28.405) B18(3.175,28.405) B19(1.905,28.405) B20(0.635,28.405) B21(-0.635,28.405) B22(-1.905,28.405) B23(-3.175,28.405) B24(-4.445,28.405) B25(-5.715,28.405) B26(-6.985,28.405) B27(-8.255,28.405) B28(-9.525,28.405) B29(-10.795,28.405) B30(-12.065,28.405) B31(-13.335,28.405) B32(-14.605,28.405) B33(-15.875,28.405) B34(-17.145,28.405) B35(-18.415,28.405) B36(-19.685,28.405) B37(-20.955,28.405) B38(-22.225,28.405) B39(-23.495,28.405) B40(-24.765,28.405) C1(24.765,29.675) C2(23.495,29.675) C3(22.225,29.675) C4(20.955,29.675) C5(19.685,29.675) C6(18.415,29.675) C7(17.145,29.675) C8(15.875,29.675) C9(14.605,29.675) C10(13.335,29.675) C11(12.065,29.675) C12(10.795,29.675) C13(9.525,29.675) C14(8.255,29.675) C15(6.985,29.675) C16(5.715,29.675) C17(4.445,29.675) C18(3.175,29.675) C19(1.905,29.675) C20(0.635,29.675) C21(-0.635,29.675) C22(-1.905,29.675) C23(-3.175,29.675) C24(-4.445,29.675) C25(-5.715,29.675) C26(-6.985,29.675) C27(-8.255,29.675) C28(-9.525,29.675) C29(-10.795,29.675) C30(-12.065,29.675) C31(-13.335,29.675) C32(-14.605,29.675) C33(-15.875,29.675) C34(-17.145,29.675) C35(-18.415,29.675) C36(-19.685,29.675) C37(-20.955,29.675) C38(-22.225,29.675) C39(-23.495,29.675) C40(-24.765,29.675) D1(24.765,30.945) D2(23.495,30.945) D3(22.225,30.945) D4(20.955,30.945) D5(19.685,30.945) D6(18.415,30.945) D7(17.145,30.945) D8(15.875,30.945) D9(14.605,30.945) D10(13.335,30.945) D11(12.065,30.945) D12(10.795,30.945) D13(9.525,30.945) D14(8.255,30.945) D15(6.985,30.945) D16(5.715,30.945) D17(4.445,30.945) D18(3.175,30.945) D19(1.905,30.945) D20(0.635,30.945) D21(-0.635,30.945) D22(-1.905,30.945) D23(-3.175,30.945) D24(-4.445,30.945) D25(-5.715,30.945) D26(-6.985,30.945) D27(-8.255,30.945) D28(-9.525,30.945) D29(-10.795,30.945) D30(-12.065,30.945) D31(-13.335,30.945) D32(-14.605,30.945) D33(-15.875,30.945) D34(-17.145,30.945) D35(-18.415,30.945) D36(-19.685,30.945) D37(-20.955,30.945) D38(-22.225,30.945) D39(-23.495,30.945) D40(-24.765,30.945) E1(24.765,32.215) E2(23.495,32.215) E3(22.225,32.215) E4(20.955,32.215) E5(19.685,32.215) E6(18.415,32.215) E7(17.145,32.215) E8(15.875,32.215) E9(14.605,32.215) E10(13.335,32.215) E11(12.065,32.215) E12(10.795,32.215) E13(9.525,32.215) E14(8.255,32.215) E15(6.985,32.215) E16(5.715,32.215) E17(4.445,32.215) E18(3.175,32.215) E19(1.905,32.215) E20(0.635,32.215) E21(-0.635,32.215) E22(-1.905,32.215) E23(-3.175,32.215) E24(-4.445,32.215) E25(-5.715,32.215) E26(-6.985,32.215) E27(-8.255,32.215) E28(-9.525,32.215) E29(-10.795,32.215) E30(-12.065,32.215) E31(-13.335,32.215) E32(-14.605,32.215) E33(-15.875,32.215) E34(-17.145,32.215) E35(-18.415,32.215) E36(-19.685,32.215) E37(-20.955,32.215) E38(-22.225,32.215) E39(-23.495,32.215) E40(-24.765,32.215) F1(24.765,33.485) F2(23.495,33.485) F3(22.225,33.485) F4(20.955,33.485) F5(19.685,33.485) F6(18.415,33.485) F7(17.145,33.485) F8(15.875,33.485) F9(14.605,33.485) F10(13.335,33.485) F11(12.065,33.485) F12(10.795,33.485) F13(9.525,33.485) F14(8.255,33.485) F15(6.985,33.485) F16(5.715,33.485) F17(4.445,33.485) F18(3.175,33.485) F19(1.905,33.485) F20(0.635,33.485) F21(-0.635,33.485) F22(-1.905,33.485) F23(-3.175,33.485) F24(-4.445,33.485) F25(-5.715,33.485) F26(-6.985,33.485) F27(-8.255,33.485) F28(-9.525,33.485) F29(-10.795,33.485) F30(-12.065,33.485) F31(-13.335,33.485) F32(-14.605,33.485) F33(-15.875,33.485) F34(-17.145,33.485) F35(-18.415,33.485) F36(-19.685,33.485) F37(-20.955,33.485) F38(-22.225,33.485) F39(-23.495,33.485) F40(-24.765,33.485) G1(24.765,34.755) G2(23.495,34.755) G3(22.225,34.755) G4(20.955,34.755) G5(19.685,34.755) G6(18.415,34.755) G7(17.145,34.755) G8(15.875,34.755) G9(14.605,34.755) G10(13.335,34.755) G11(12.065,34.755) G12(10.795,34.755) G13(9.525,34.755) G14(8.255,34.755) G15(6.985,34.755) G16(5.715,34.755) G17(4.445,34.755) G18(3.175,34.755) G19(1.905,34.755) G20(0.635,34.755) G21(-0.635,34.755) G22(-1.905,34.755) G23(-3.175,34.755) G24(-4.445,34.755) G25(-5.715,34.755) G26(-6.985,34.755) G27(-8.255,34.755) G28(-9.525,34.755) G29(-10.795,34.755) G30(-12.065,34.755) G31(-13.335,34.755) G32(-14.605,34.755) G33(-15.875,34.755) G34(-17.145,34.755) G35(-18.415,34.755) G36(-19.685,34.755) G37(-20.955,34.755) G38(-22.225,34.755) G39(-23.495,34.755) G40(-24.765,34.755) H1(24.765,36.025) H2(23.495,36.025) H3(22.225,36.025) H4(20.955,36.025) H5(19.685,36.025) H6(18.415,36.025) H7(17.145,36.025) H8(15.875,36.025) H9(14.605,36.025) H10(13.335,36.025) H11(12.065,36.025) H12(10.795,36.025) H13(9.525,36.025) H14(8.255,36.025) H15(6.985,36.025) H16(5.715,36.025) H17(4.445,36.025) H18(3.175,36.025) H19(1.905,36.025) H20(0.635,36.025) H21(-0.635,36.025) H22(-1.905,36.025) H23(-3.175,36.025) H24(-4.445,36.025) H25(-5.715,36.025) H26(-6.985,36.025) H27(-8.255,36.025) H28(-9.525,36.025) H29(-10.795,36.025) H30(-12.065,36.025) H31(-13.335,36.025) H32(-14.605,36.025) H33(-15.875,36.025) H34(-17.145,36.025) H35(-18.415,36.025) H36(-19.685,36.025) H37(-20.955,36.025) H38(-22.225,36.025) H39(-23.495,36.025) H40(-24.765,36.025) J1(24.765,37.295) J2(23.495,37.295) J3(22.225,37.295) J4(20.955,37.295) J5(19.685,37.295) J6(18.415,37.295) J7(17.145,37.295) J8(15.875,37.295) J9(14.605,37.295) J10(13.335,37.295) J11(12.065,37.295) J12(10.795,37.295) J13(9.525,37.295) J14(8.255,37.295) J15(6.985,37.295) J16(5.715,37.295) J17(4.445,37.295) J18(3.175,37.295) J19(1.905,37.295) J20(0.635,37.295) J21(-0.635,37.295) J22(-1.905,37.295) J23(-3.175,37.295) J24(-4.445,37.295) J25(-5.715,37.295) J26(-6.985,37.295) J27(-8.255,37.295) J28(-9.525,37.295) J29(-10.795,37.295) J30(-12.065,37.295) J31(-13.335,37.295) J32(-14.605,37.295) J33(-15.875,37.295) J34(-17.145,37.295) J35(-18.415,37.295) J36(-19.685,37.295) J37(-20.955,37.295) J38(-22.225,37.295) J39(-23.495,37.295) J40(-24.765,37.295) K1(24.765,38.565) K2(23.495,38.565) K3(22.225,38.565) K4(20.955,38.565) K5(19.685,38.565) K6(18.415,38.565) K7(17.145,38.565) K8(15.875,38.565) K9(14.605,38.565) K10(13.335,38.565) K11(12.065,38.565) K12(10.795,38.565) K13(9.525,38.565) K14(8.255,38.565) K15(6.985,38.565) K16(5.715,38.565) K17(4.445,38.565) K18(3.175,38.565) K19(1.905,38.565) K20(0.635,38.565) K21(-0.635,38.565) K22(-1.905,38.565) K23(-3.175,38.565) K24(-4.445,38.565) K25(-5.715,38.565) K26(-6.985,38.565) K27(-8.255,38.565) K28(-9.525,38.565) K29(-10.795,38.565) K30(-12.065,38.565) K31(-13.335,38.565) K32(-14.605,38.565) K33(-15.875,38.565) K34(-17.145,38.565) K35(-18.415,38.565) K36(-19.685,38.565) K37(-20.955,38.565) K38(-22.225,38.565) K39(-23.495,38.565) K40(-24.765,38.565)
  round 4 hole 4 unplated paste-2539.97 mask+0: ""(-34.5,32.85) ""(-34.5,-32.85) ""(34.5,32.85) ""(34.5,-32.85)
  round 8 hole 4 paste-2539.97 mask+0: ""(-34,65.5) ""(-34,-65.5) ""(34,65.5) ""(34,-65.5)
  round 3.5 hole 3.5 unplated paste-2539.97 mask+0: ""(7.2,63.75)
  oval 3.5x5 hole 3.5 slot 5 at 90 deg unplated paste-2539.97 mask+0: ""(7.2,-63)
  silkscreen extent -39,-70 39,70
TC3216-1206 [mm] "Capacitor, SM Tantalum; Body 3.2 x 1.6 mm (LxW typ)"
  rect 1.4x1.2 smd mask+0: 1(-1.1,0) 2(1.1,0)
  silkscreen extent -2.32,-0.9 1.7,0.9, body extent -1.7,-0.84 1.7,0.84, height 1.71
TP_50mil [mm]
  round 1.27 smd mask+0: 1(0,0)
TP_HS#1 [mm]
  round 0.5 smd paste+0 mask+0: 1(0,0)
  GND pour cut-out: 0,0.254 0.097,0.235 0.18,0.18 0.235,0.097 0.254,0 0.254,0 0.235,-0.097 0.18,-0.18 0.097,-0.235 0,-0.254 0,-0.254 -0.097,-0.235 -0.18,-0.18 -0.235,-0.097 -0.254,0 -0.254,0 -0.235,0.097 -0.18,0.18 -0.097,0.235 0,0.254
TP_HS#2 [mm]
  round 0.5 smd paste+0 mask+0: 1(0,0)
  PWR pour cut-out: 0,0.254 0.097,0.235 0.18,0.18 0.235,0.097 0.254,0 0.254,0 0.235,-0.097 0.18,-0.18 0.097,-0.235 0,-0.254 0,-0.254 -0.097,-0.235 -0.18,-0.18 -0.235,-0.097 -0.254,0 -0.254,0 -0.235,0.097 -0.18,0.18 -0.097,0.235 0,0.254
TP_HS#3 [mm]
  round 0.5 smd paste+0 mask+0: 1(0,-0.1)
  PWR pour cut-out: 0,0.154 0.097,0.135 0.18,0.08 0.235,-0.003 0.254,-0.1 0.254,-0.1 0.235,-0.197 0.18,-0.28 0.097,-0.335 0,-0.354 0,-0.354 -0.097,-0.335 -0.18,-0.28 -0.235,-0.197 -0.254,-0.1 -0.254,-0.1 -0.235,-0.003 -0.18,0.08 -0.097,0.135 0,0.154
TP_HS#4 [mm]
  round 0.5 smd paste+0 mask+0: 1(0.046,0.1)
  PWR pour cut-out: 0,0.354 0.097,0.335 0.18,0.28 0.235,0.197 0.254,0.1 0.254,0.1 0.235,0.003 0.18,-0.08 0.097,-0.135 0,-0.154 0,-0.154 -0.097,-0.135 -0.18,-0.08 -0.235,0.003 -0.254,0.1 -0.254,0.1 -0.235,0.197 -0.18,0.28 -0.097,0.335 0,0.354
TP_HS#5 [mm]
  round 0.5 smd paste+0 mask+0: 1(0,-0.779)
  GND pour cut-out: 0,-0.524 0.097,-0.544 0.18,-0.599 0.235,-0.681 0.254,-0.778 0.254,-0.778 0.235,-0.875 0.18,-0.958 0.097,-1.013 0,-1.032 0,-1.032 -0.097,-1.013 -0.18,-0.958 -0.235,-0.875 -0.254,-0.778 -0.254,-0.778 -0.235,-0.681 -0.18,-0.599 -0.097,-0.544 0,-0.524
TP_HS#6 [mm]
  round 0.5 smd paste+0 mask+0: 1(0,-0.779)
  PWR pour cut-out: 0,-0.523 0.097,-0.543 0.18,-0.598 0.235,-0.68 0.254,-0.777 0.254,-0.777 0.235,-0.875 0.18,-0.957 0.097,-1.012 0,-1.031 0,-1.031 -0.097,-1.012 -0.18,-0.957 -0.235,-0.875 -0.254,-0.777 -0.254,-0.777 -0.235,-0.68 -0.18,-0.598 -0.097,-0.543 0,-0.523
TP_HS#7 [mm]
  round 0.5 smd paste+0 mask+0: 1(0,0.065)
  GND pour cut-out: 0,0.315 0.097,0.295 0.18,0.24 0.235,0.158 0.254,0.061 0.254,0.061 0.235,-0.037 0.18,-0.119 0.097,-0.174 0,-0.193 0,-0.193 -0.097,-0.174 -0.18,-0.119 -0.235,-0.037 -0.254,0.061 -0.254,0.061 -0.235,0.158 -0.18,0.24 -0.097,0.295 0,0.315
TP_HS#8 [mm]
  round 0.5 smd paste+0 mask+0: 1(-0.025,0)
  GND pour cut-out: 0,0.254 0.097,0.235 0.18,0.18 0.235,0.097 0.254,0 0.254,0 0.235,-0.097 0.18,-0.18 0.097,-0.235 0,-0.254 0,-0.254 -0.097,-0.235 -0.18,-0.18 -0.235,-0.097 -0.254,0 -0.254,0 -0.235,0.097 -0.18,0.18 -0.097,0.235 0,0.254
TP_HS#9 [mm]
  round 0.5 smd mask+0: 1(0,0)
  PWR pour cut-out: 0,0.254 0.097,0.235 0.18,0.18 0.235,0.097 0.254,0 0.254,0 0.235,-0.097 0.18,-0.18 0.097,-0.235 0,-0.254 0,-0.254 -0.097,-0.235 -0.18,-0.18 -0.235,-0.097 -0.254,0 -0.254,0 -0.235,0.097 -0.18,0.18 -0.097,0.235 0,0.254
TP_HS#10 [mm]
  round 0.5 smd mask+0: 1(0,0)
  GND pour cut-out: 0,0.254 0.097,0.235 0.18,0.18 0.235,0.097 0.254,0 0.254,0 0.235,-0.097 0.18,-0.18 0.097,-0.235 0,-0.254 0,-0.254 -0.097,-0.235 -0.18,-0.18 -0.235,-0.097 -0.254,0 -0.254,0 -0.235,0.097 -0.18,0.18 -0.097,0.235 0,0.254
USB-269-BRW [mm] "LCSC C720548"
  round 1.6 hole 1 paste-2539.97 mask+0: 1(3.5,0.47) 2(1,0.47) 3(-1,0.47) 4(-3.5,0.47) 5(3.5,2.97) 6(1,2.97) 7(-1,2.97) 8(-3.5,2.97)
  round 3.5 hole 2.5 paste-2539.97 mask+0: 9(-6.55,5.68) 10(-6.55,0) 11(6.55,0) 12(6.55,5.68)
  silkscreen extent -7.75,1.5 7.75,15, body extent -7.8,-1.1 7.8,16.1, height 17.15
XT60PB-M [mm]
  round 5.516 hole 4.5 slot 4.505 at 0 deg mask+0: 1(3.6,0) 2(-3.6,0)
  silkscreen extent -8,-4 8,4, body extent -8.03,-4.03 7.97,4.07, height 16
XUBF-1800-0610 [mm]
  round 1.2 hole 0.6 mask+0: 1(-3.5,2) 2(-1,2) 3(1,2) 4(3.5,2) 5(4,3.5) 6(2,3.5) 7(0,3.5) 8(-2,3.5) 9(-4,3.5) 10(-3.5,5.2) 11(-1,5.2) 12(1,5.2) 13(3.5,5.2) 14(4,6.7) 15(2,6.7) 16(0,6.7) 17(-2,6.7) 18(-4,6.7)
  oval 2.9x3.5 hole 1.8 slot 2.4 at 90 deg mask+0: 19(-6.6,0) 20(6.6,0) 21(-6.6,5.68) 22(6.6,5.68)
  silkscreen extent -6.6,-9.3 6.6,7.9, body extent -7.5,-9.63 7.5,7.81, height 16.21
带灯按键 [mm]
  round 1.8 hole 1.2 mask+0.05: 1(-2.5,0) 2(2.5,0) 3(0,2.5) 4(0,0)
  silkscreen extent -3.9,-4.7 3.9,4.3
